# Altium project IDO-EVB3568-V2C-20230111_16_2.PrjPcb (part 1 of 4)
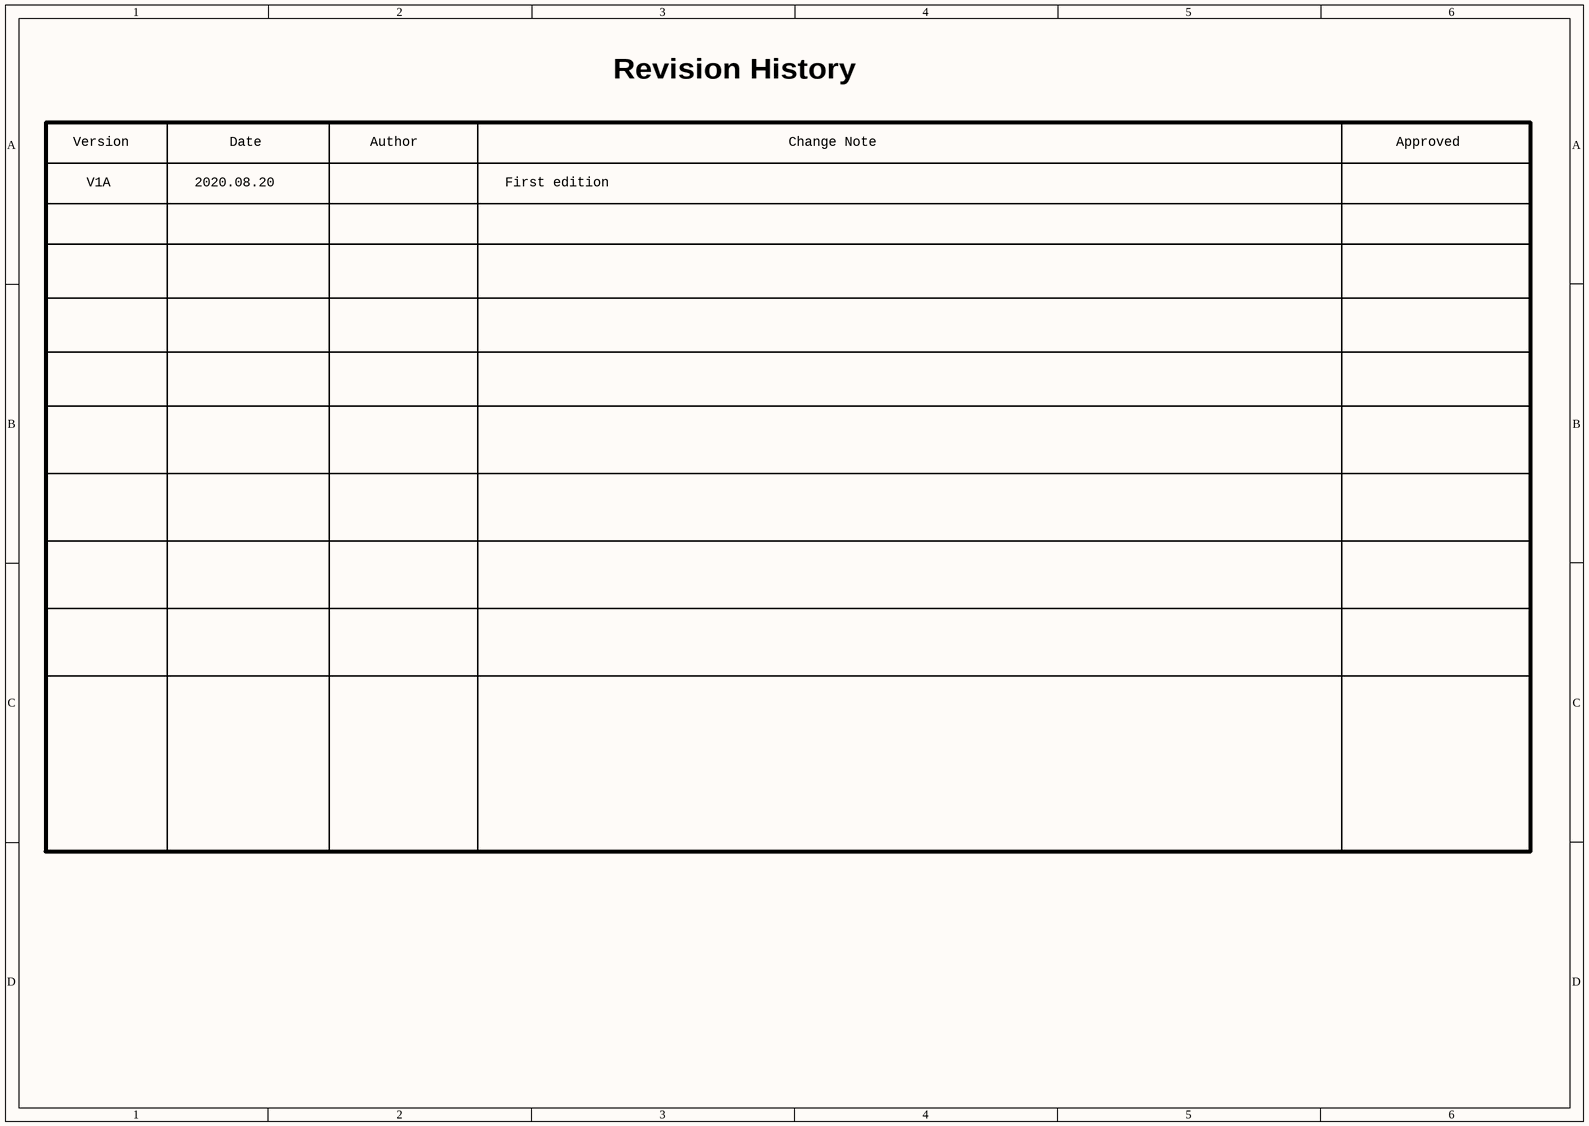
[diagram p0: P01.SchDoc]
20 sheets, 809 parts. Net scope: global (net labels, ports and power ports of the same name join across sheets).
Sheets:
  P01.SchDoc
  P02.SchDoc
  P03.SchDoc
  P04.SchDoc
  P05.SchDoc
  P06.SchDoc
  P07.SchDoc
  P08.SchDoc
  P09.SchDoc
  P10.SchDoc
  P11.SchDoc
  P12.SchDoc
  P13.SchDoc
  P14.SchDoc
  P15.SchDoc
  P16.SchDoc
  P17.SchDoc
  P18.SchDoc
  P19.SchDoc
  P20.SchDoc

## Sheet P01.SchDoc
size 297 x 209 mm

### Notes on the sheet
- Revision History
- Version
- V1A
- 2020.08.20
- Date
- Author
- First edition
- Change Note
- Approved

## Sheet P02.SchDoc
size 594 x 420 mm
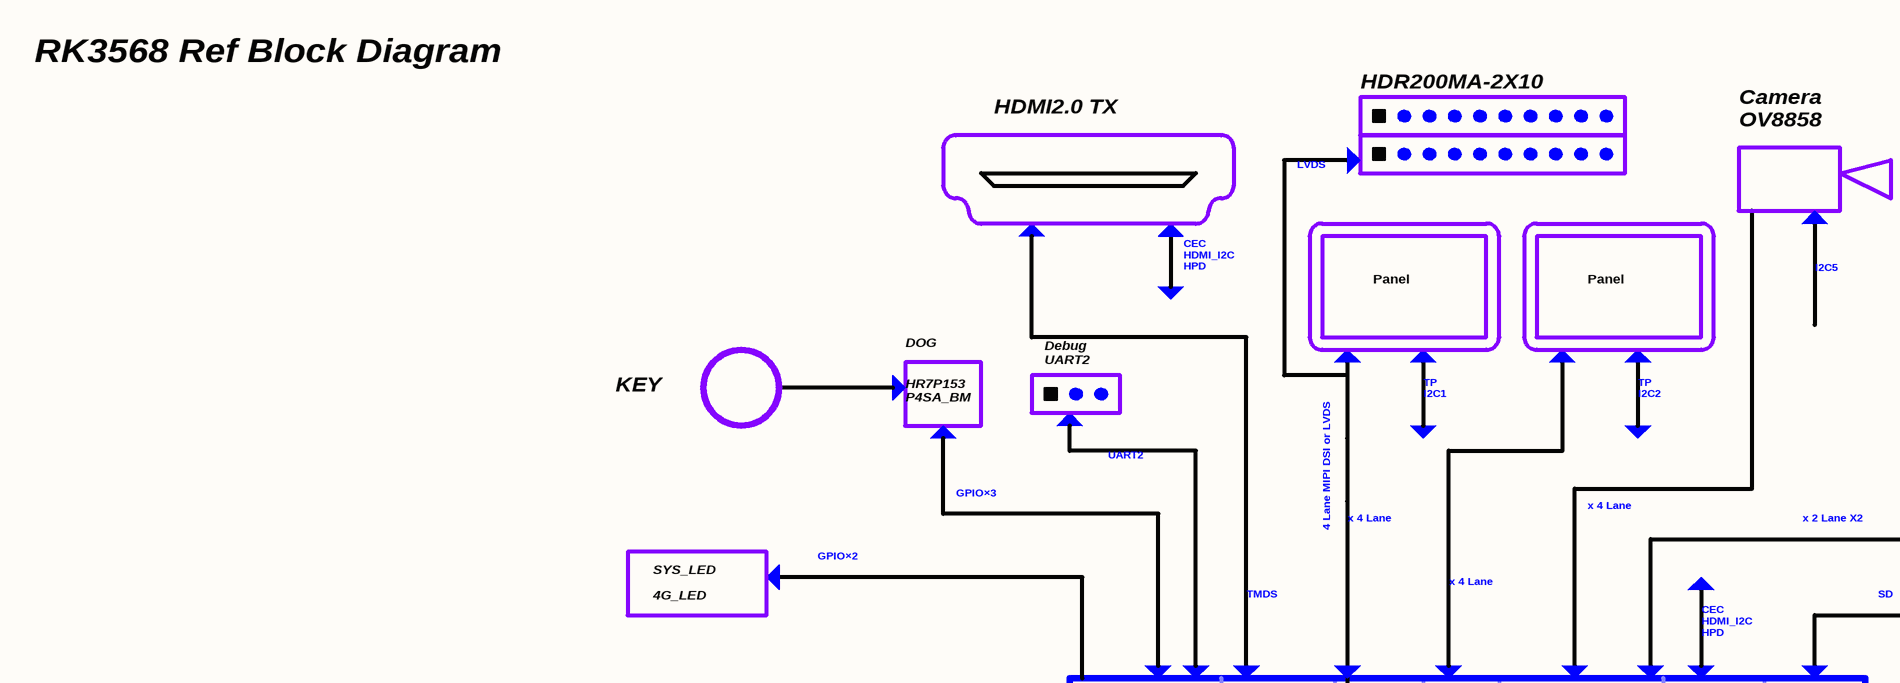
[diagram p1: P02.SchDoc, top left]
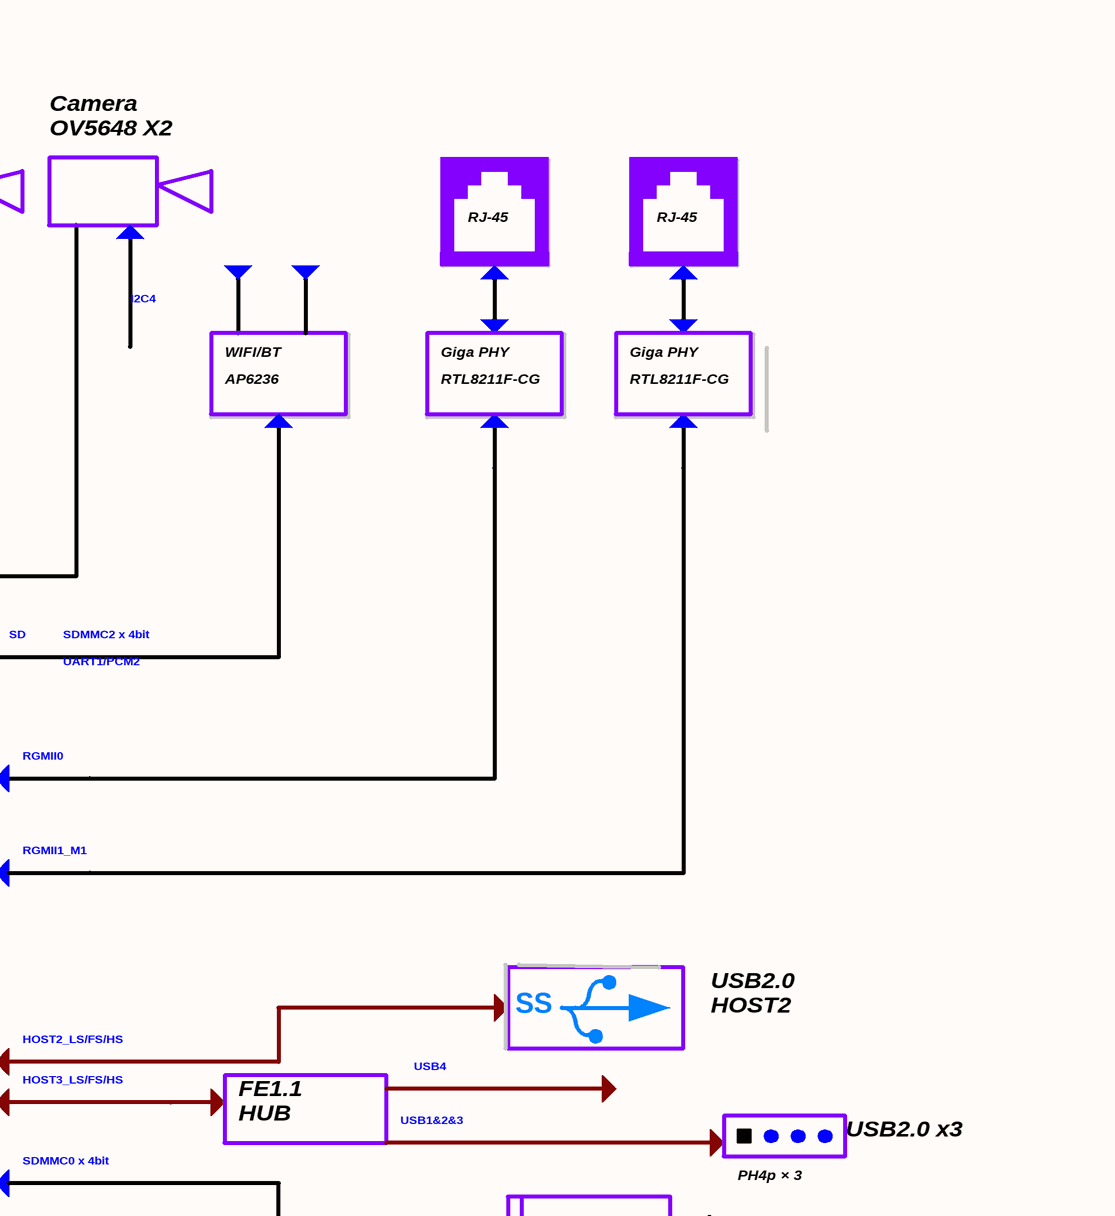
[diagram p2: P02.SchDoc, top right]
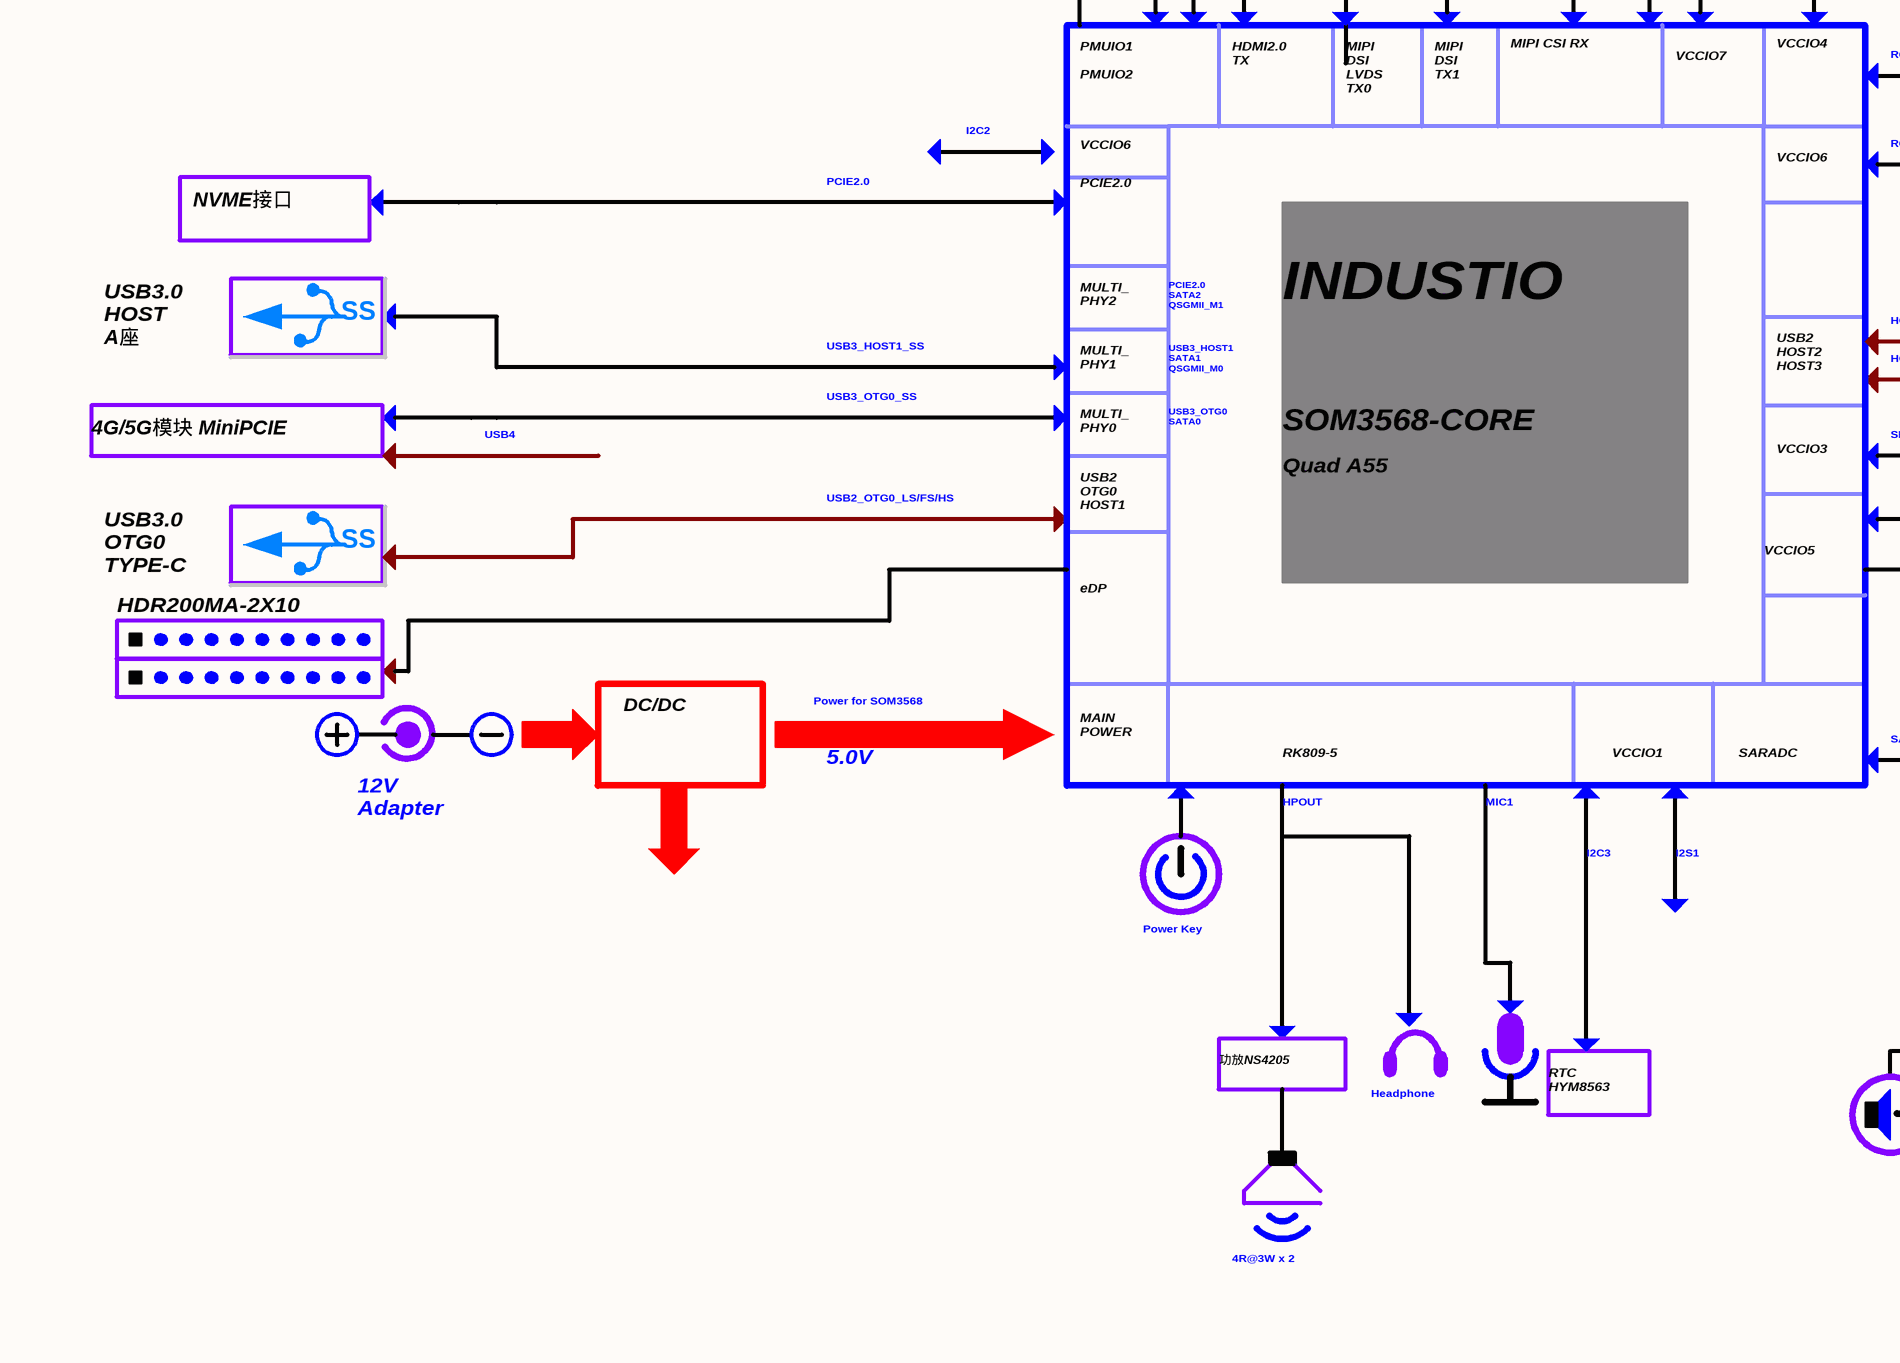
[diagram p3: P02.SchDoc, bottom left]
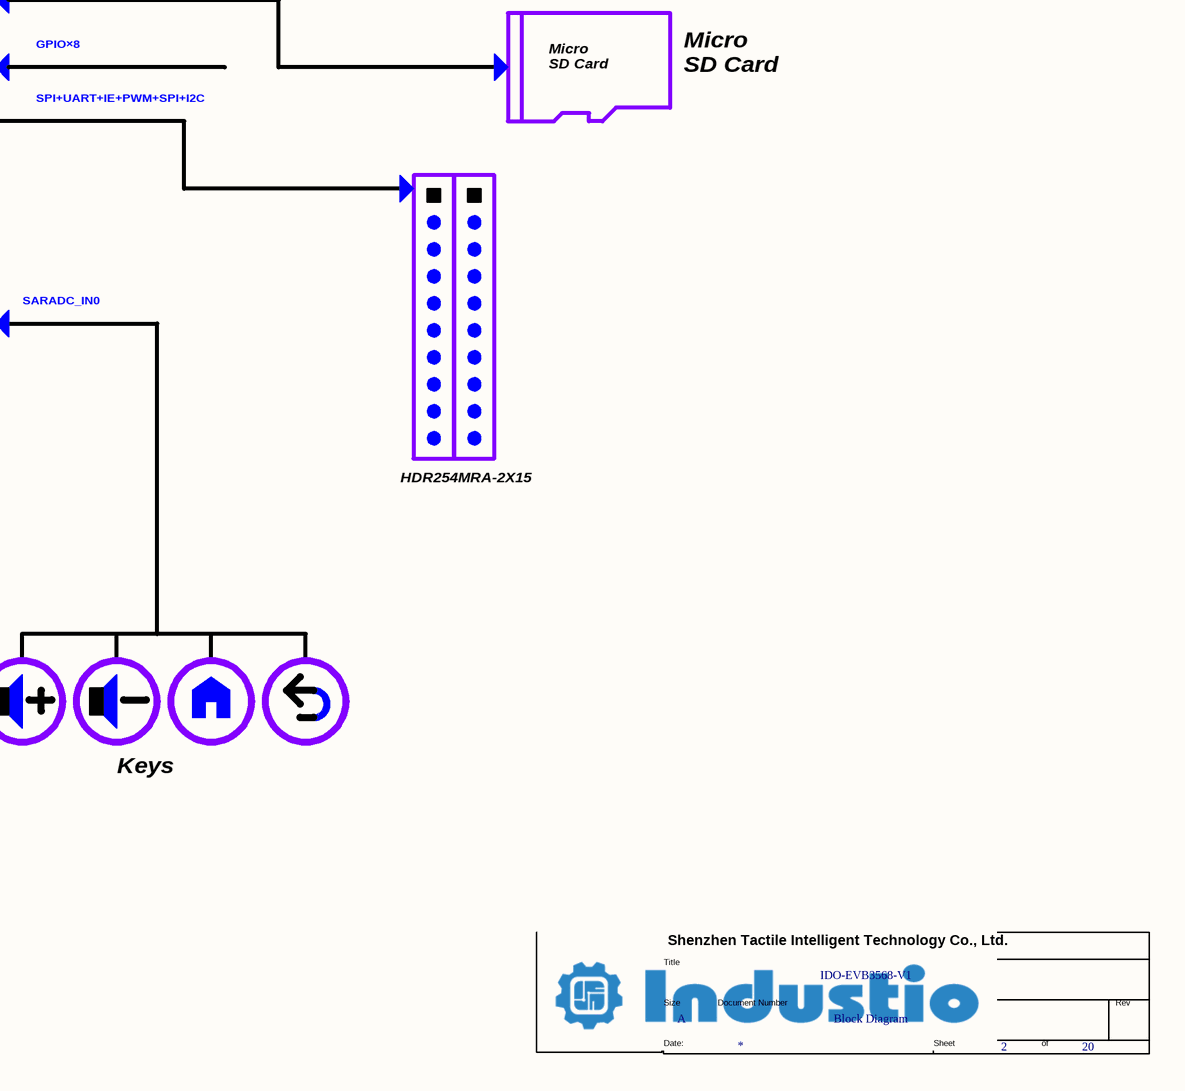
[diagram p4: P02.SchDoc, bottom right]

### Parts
(Parts that share a designator on the sheet are numbered #1, #2 ... from top to bottom, then left to right.)
*#1  Doc: Block Diagram  Title: IDO-EVB3568-V1  Page Size: A  Page Number: 2  Page Count: 20  (hidden comment: TitleBlock1)  (graphical)

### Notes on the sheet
- RK3568 Ref Block Diagram
- HDR200MA-2X10
- Camera
  OV8858
- Camera
  OV5648 X2
- HDMI2.0 TX
- LVDS
- CEC
  HDMI_I2C
  HPD
- RJ-45
- Panel
- I2C5
- I2C4
- DOG
- Debug
  UART2
- AP6236
- WIFI/BT
- RTL8211F-CG
- Giga PHY
- KEY
- HR7P153
  P4SA_BM
- TP
  I2C1
- TP
  I2C2
- UART2
- GPIO×3
- 4 Lane MIPI DSI or LVDS
- x 4 Lane
- x 2 Lane X2
- 4G_LED
- SYS_LED
- GPIO×2
- TMDS
- SD
- SDMMC2 x 4bit
- UART1/PCM2
- PMUIO1
  PMUIO2
- HDMI2.0
  TX
- MIPI
  DSI
  LVDS
  TX0
- MIPI
  DSI
  TX1
- MIPI CSI RX
- VCCIO7
- VCCIO4
- RGMII0
- I2C2
- VCCIO6
- RGMII1_M1
- NVME接口
- PCIE2.0
- USB3.0
  HOST
  A座
- MULTI_
  PHY2
- PCIE2.0
  SATA2
  QSGMII_M1
- USB2.0
  HOST2
- SS
- MULTI_
  PHY1
- USB3_HOST1
  SATA1
  QSGMII_M0
- INDUSTIO
- USB2
  HOST2
  HOST3
- HOST2_LS/FS/HS
- USB3_OTG0_SS
- USB3_HOST1_SS
- MULTI_
  PHY0
- USB3_OTG0
  SATA0
- HOST3_LS/FS/HS
- FE1.1
  HUB
- USB1&2&3
- USB4
- USB2.0 x3
- 4G/5G模块 MiniPCIE
- USB2
  OTG0
  HOST1
- SOM3568-CORE
- VCCIO3
- SDMMC0 x 4bit
- PH4p × 3
- USB3.0
  OTG0
  TYPE-C
- USB2_OTG0_LS/FS/HS
- Quad A55
- GPIO×8
- Micro
  SD Card
- eDP
- VCCIO5
- SPI+UART+IE+PWM+SPI+I2C
- DC/DC
- Power for SOM3568
- MAIN
  POWER
- 12V
  Adapter
- 5.0V
- RK809-5
- VCCIO1
- SARADC
- SARADC_IN0
- HPOUT
- MIC1
- I2C3
- I2S1
- HDR254MRA-2X15
- Power Key
- 功放NS4205
- Headphone
- RTC
  HYM8563
- Keys
- 4R@3W x 2

## Sheet P03.SchDoc
size 594 x 420 mm
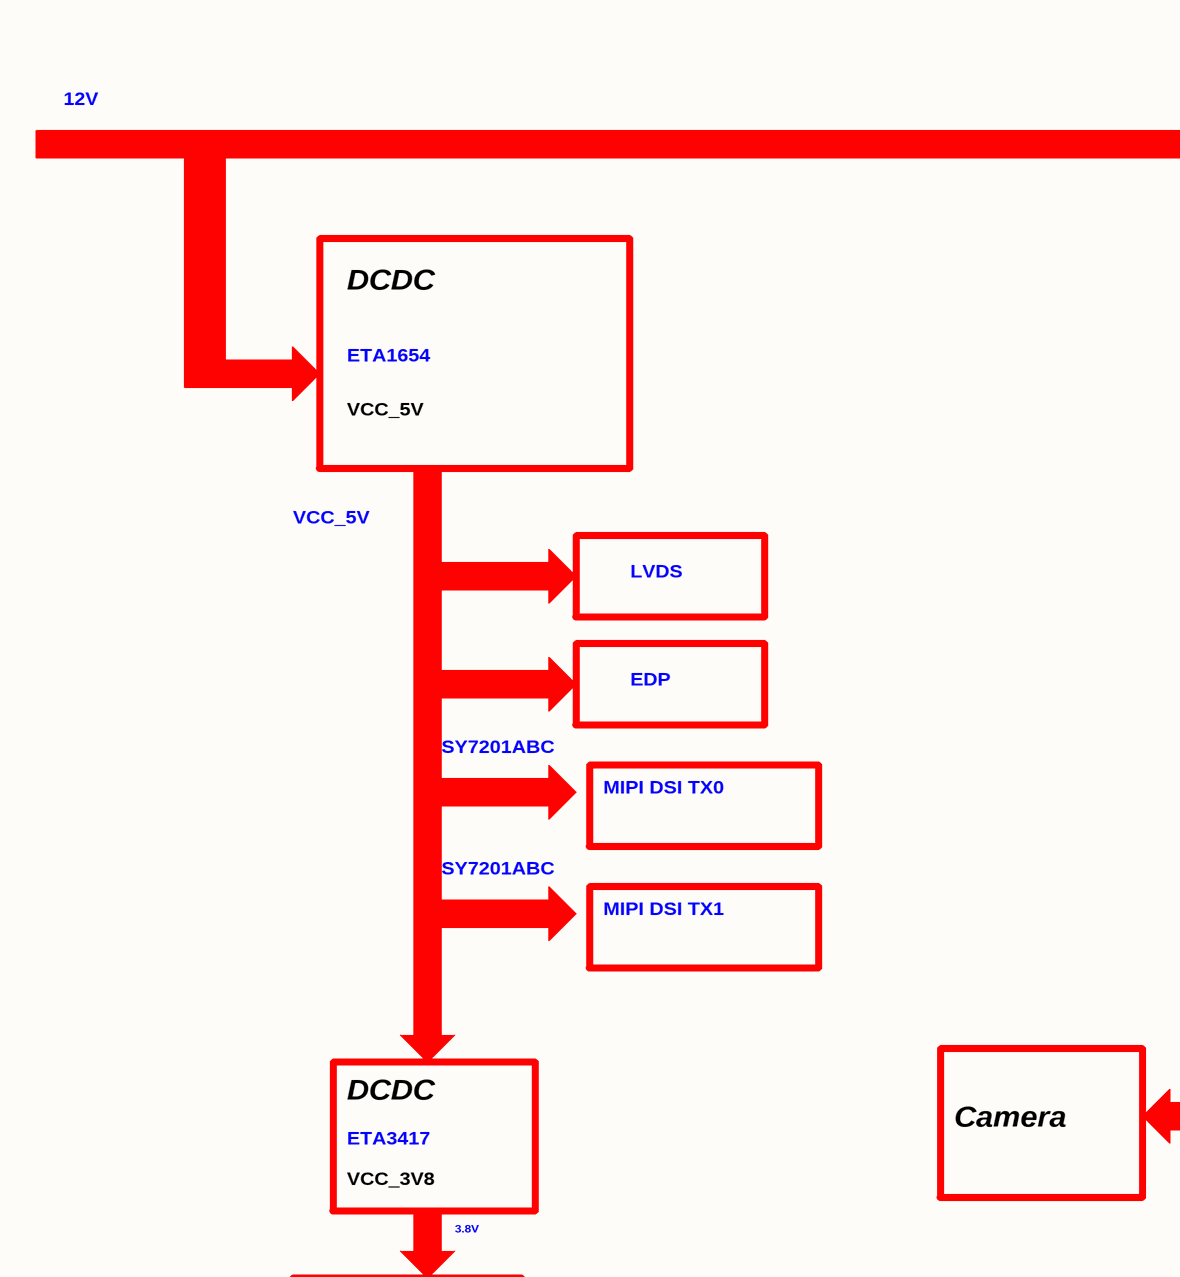
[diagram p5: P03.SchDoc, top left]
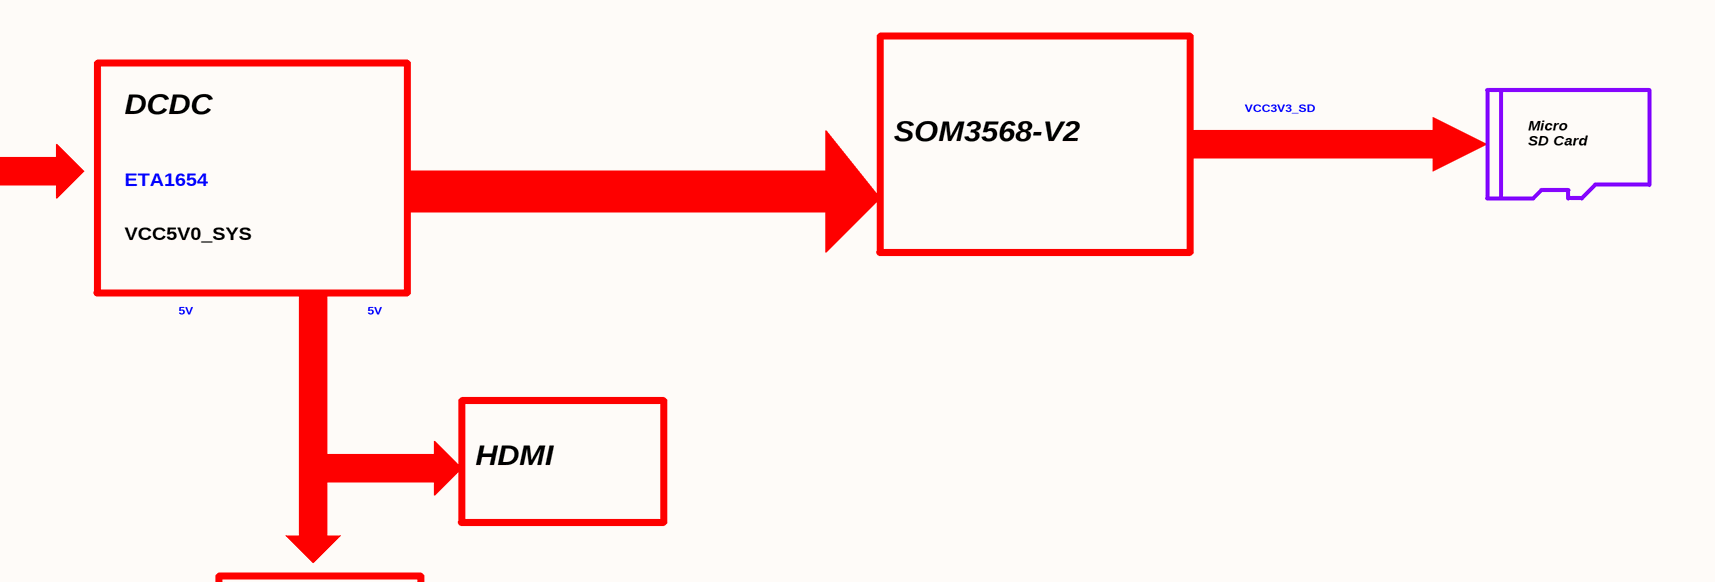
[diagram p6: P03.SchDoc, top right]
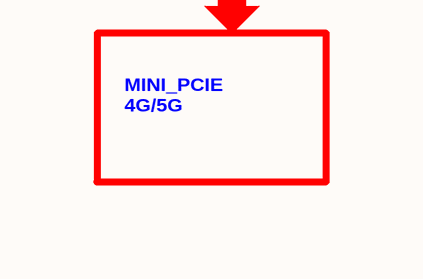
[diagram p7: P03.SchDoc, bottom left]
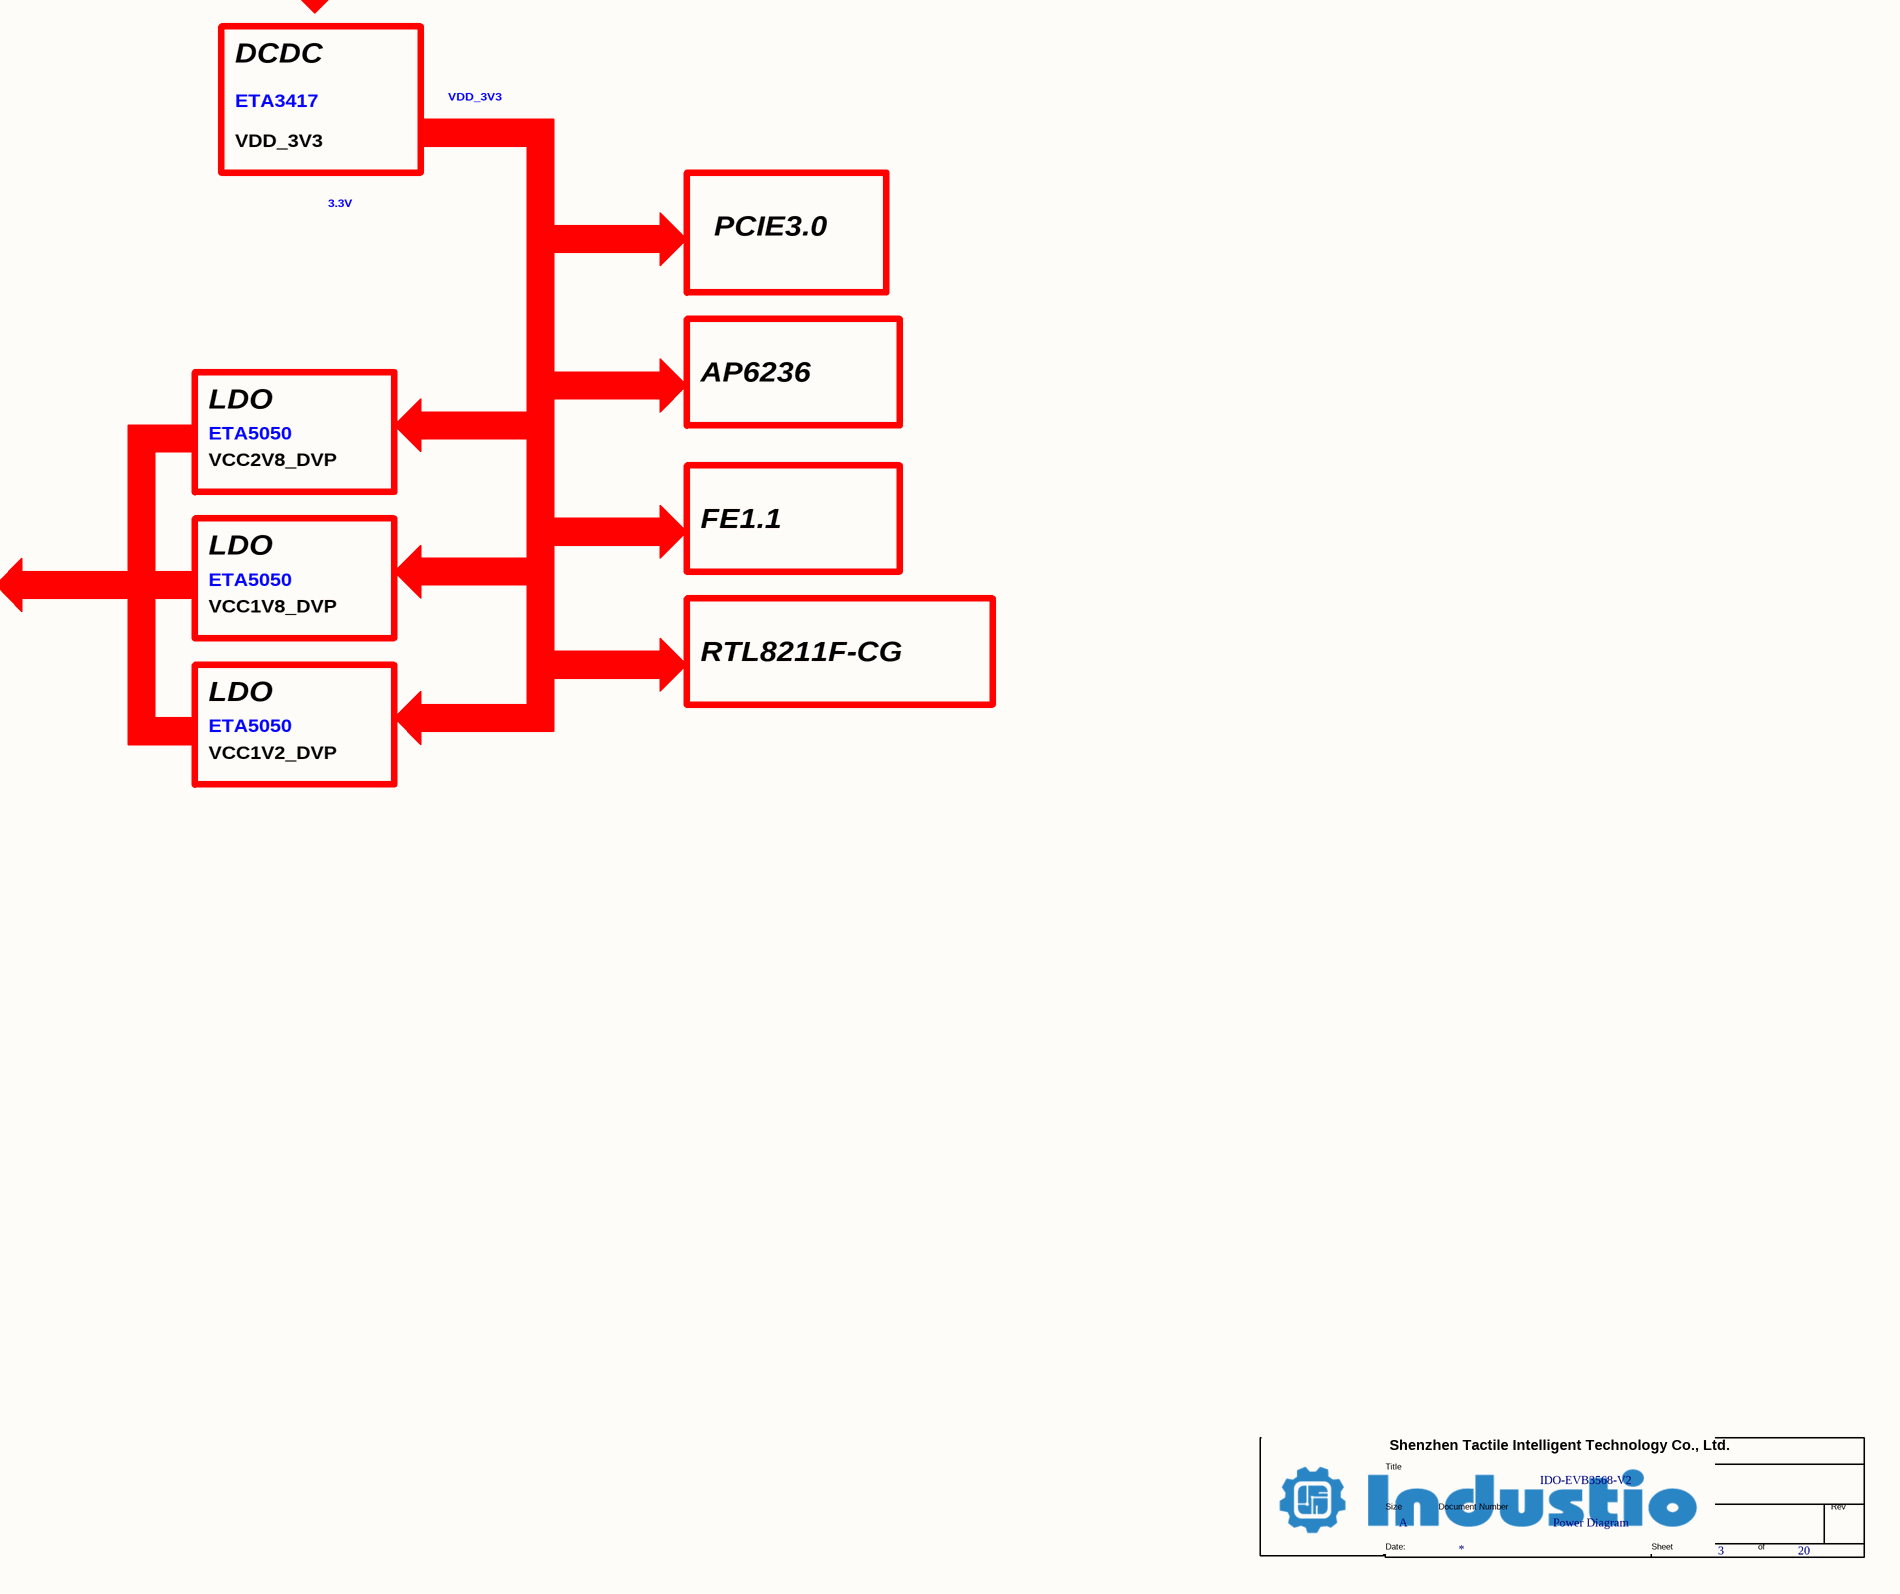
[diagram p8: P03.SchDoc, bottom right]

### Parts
(Parts that share a designator on the sheet are numbered #1, #2 ... from top to bottom, then left to right.)
*#2  Doc: Power Diagram  Title: IDO-EVB3568-V2  Page Size: A  Page Number: 3  Page Count: 20  (hidden comment: TitleBlock1)  (graphical)

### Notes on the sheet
- 12V
- DCDC
- SOM3568-V2
- VCC3V3_SD
- Micro
  SD Card
- ETA1654
- VCC5V0_SYS
- 5V
- VCC_5V
- HDMI
- LVDS
- ETA3417
- VDD_3V3
- EDP
- SY7201ABC
- MIPI DSI TX0
- 3.3V
- PCIE3.0
- MIPI DSI TX1
- AP6236
- LDO
- ETA5050
- VCC2V8_DVP
- FE1.1
- Camera
- VCC_3V8
- VCC1V8_DVP
- RTL8211F-CG
- 3.8V
- MINI_PCIE
  4G/5G
- VCC1V2_DVP

## Sheet P04.SchDoc
size 420 x 297 mm
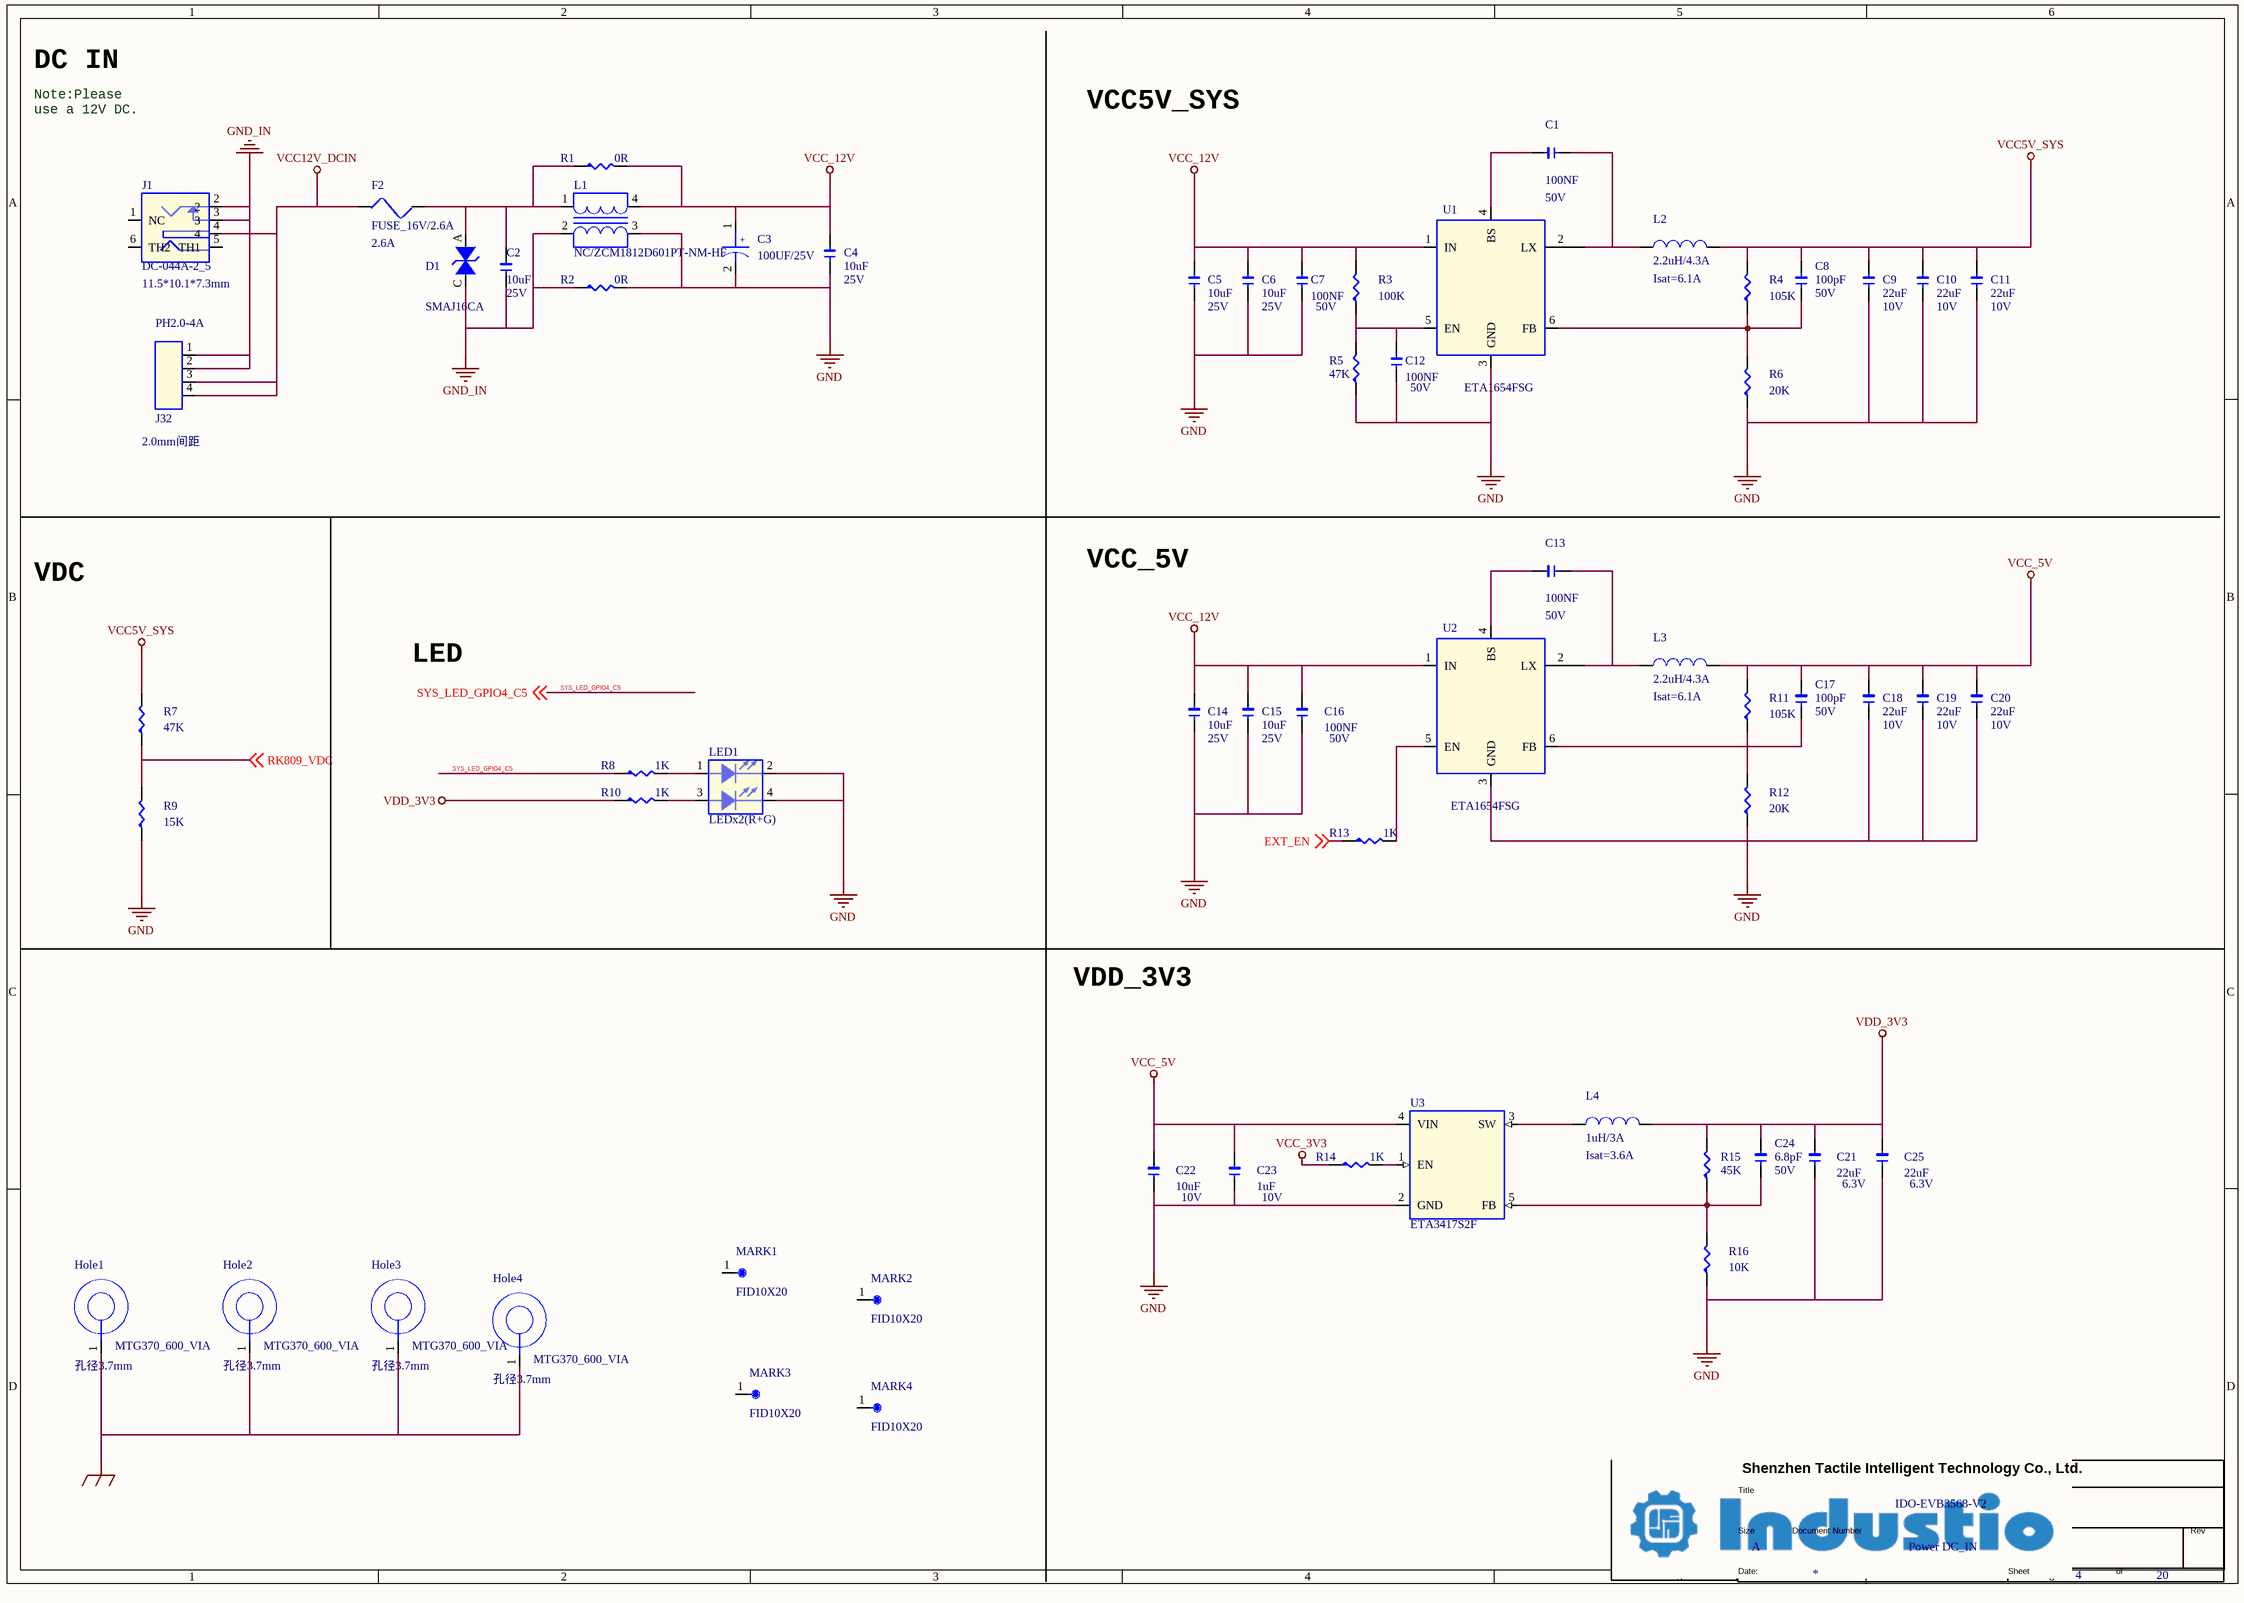
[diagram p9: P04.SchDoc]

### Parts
(Parts that share a designator on the sheet are numbered #1, #2 ... from top to bottom, then left to right.)
*#3  Doc: Power DC_IN  Title: IDO-EVB3568-V2  Page Size: A  Page Number: 4  Page Count: 20  (hidden comment: TitleBlock1)  (graphical)
C1  100NF  DSC2: 50V  [1206]
C2  10uF  DSC2: 25V  [1206]
C3  100UF/25V  [CAPAE660X770]
C4  10uF  DSC2: 25V  [1206]
C5  10uF  DSC2: 25V  [1206]
C6  10uF  DSC2: 25V  [1206]
C7  100NF  DSC2: 50V  [1206]
C8  100pF  DSC2: 50V  [1206]
C9  22uF  DSC2: 10V  [1206]
C10  22uF  DSC2: 10V  [1206]
C11  22uF  DSC2: 10V  [1206]
C12  100NF  DSC2: 50V  [1206]
C13  100NF  DSC2: 50V  [1206]
C14  10uF  DSC2: 25V  [1206]
C15  10uF  DSC2: 25V  [1206]
C16  100NF  DSC2: 50V  [1206]
C17  100pF  DSC2: 50V  [1206]
C18  22uF  DSC2: 10V  [1206]
C19  22uF  DSC2: 10V  [1206]
C20  22uF  DSC2: 10V  [1206]
C21  22uF  DSC2: 6.3V  [1206]
C22  10uF  DSC2: 10V  [1206]
C23  1uF  DSC2: 10V  [1206]
C24  6.8pF  DSC2: 50V  [1206]
C25  22uF  DSC2: 6.3V  [1206]
D1  SMAJ16CA  [SMA_DO-214AC]
F2  FUSE_16V/2.6A  DSC2: 2.6A  [SMD1812]
Hole1  MTG370_600_VIA  DSC2: 孔径3.7mm  [MH276_091]
Hole2  MTG370_600_VIA  DSC2: 孔径3.7mm  [MH276_091]
Hole3  MTG370_600_VIA  DSC2: 孔径3.7mm  [MH276_091]
Hole4  MTG370_600_VIA  DSC2: 孔径3.7mm  [MH276_091]
J1  DC-044A-2_5  DSC2: 11.5*10.1*7.3mm  [DC-044A-2_0-DIP]
J32  PH2.0-4A  DSC2: 2.0mm间距  [PH200-4A]
L1  NC/ZCM1812D601PT-NM-HF  [CMLP-ACM4532]
L2  2.2uH/4.3A  DSC2: Isat=6.1A  [IND_404020]
L3  2.2uH/4.3A  DSC2: Isat=6.1A  [IND_404020]
L4  1uH/3A  DSC2: Isat=3.6A  [IND_252012]
LED1  LEDx2(R+G)  [LED_P254_2X2DIP]
MARK1  FID10X20  [E-Mark-TP-02-100x]
MARK2  FID10X20  [E-Mark-TP-02-100x]
MARK3  FID10X20  [E-Mark-TP-02-100x]
MARK4  FID10X20  [E-Mark-TP-02-100x]
R1  0R  [R0805]
R2  0R  [R0805]
R3  100K  [R0402]
R4  105K  [R0402]
R5  47K  [R0402]
R6  20K  [R0402]
R7  47K  [R0402]
R8  1K  [R0402]
R9  15K  [R0402]
R10  1K  [R0402]
R11  105K  [R0402]
R12  20K  [R0402]
R13  1K  [R0402]
R14  1K  [R0402]
R15  45K  [R0402]
R16  10K  [R0402]
U1  ETA1654FSG  [SOT563]
U2  ETA1654FSG  [SOT563]
U3  ETA3417S2F  [SOT23-5]

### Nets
GND: C3.2 C4.1 C5.1 C6.1 C7.1 C9.1 C10.1 C11.1 C12.1 C14.1 C15.1 C16.1 C18.1 C19.1 C20.1 C21.1 C22.1 C23.1 C25.1 L1.3 LED1.2 LED1.4 R2.2 R5.1 R6.1 R9.1 R12.1 R16.1 U1.3(GND) U2.3(GND) U3.2(GND)  [project net EDP_TX_AUXP_]
GND_EARTH: Hole1.1 Hole2.1 Hole3.1 Hole4.1
GND_IN: C2.1 D1.C(I/O1) J1.2 J1.3 J32.1 J32.2 L1.2 R2.1
VCC5V_SYS: C8.2 C9.2 C10.2 C11.2 L2.2 R4.2 R7.2
VCC12V_DCIN: F2.1 J1.4 J32.3 J32.4
VCC_3V3: R14.1
VCC_5V: C17.2 C18.2 C19.2 C20.2 C22.2 C23.2 L3.2 R11.2 U3.4(VIN)
VCC_12V: C3.1 C4.2 C5.2 C6.2 C7.2 C14.2 C15.2 C16.2 L1.4 R1.2 R3.2 U1.1(IN) U2.1(IN)
VDD_3V3: C21.2 C24.2 C25.2 L4.2 R10.1 R15.2
EXT_EN: R13.1 ; off-sheet EXT_EN
RK809_VDC: R7.1 R9.2 ; off-sheet RK809_VDC
SYS_LED_GPIO4_C5: R8.1 ; off-sheet SYS_LED_GPIO4_C5
NetC1_1: C1.1 L2.1 U1.2(LX)
NetC1_2: C1.2 U1.4(BS)
NetC2_2: C2.2 D1.A(I/O2) F2.2 L1.1 R1.1
NetC8_1: C8.1 R4.1 R6.2 U1.6(FB)
NetC12_2: C12.2 R3.1 R5.2 U1.5(EN)
NetC13_1: C13.1 L3.1 U2.2(LX)
NetC13_2: C13.2 U2.4(BS)
NetC17_1: C17.1 R11.1 R12.2 U2.6(FB)
NetC24_1: C24.1 R15.1 R16.2 U3.5(FB)
NetL4_1: L4.1 U3.3(SW)
NetLED1_1: LED1.1 R8.2
NetLED1_3: LED1.3 R10.2
NetR13_2: R13.2 U2.5(EN)
NetR14_2: R14.2 U3.1(EN)

Not connected (* = marked no-connect by the designer): J1 1(NC) 5(TH1) 6(TH2); MARK1 1; MARK2 1; MARK3 1; MARK4 1

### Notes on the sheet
- DC IN
- Note:Please
  use a 12V DC.
- VCC5V_SYS
- VDC
- VCC_5V
- LED
- VDD_3V3

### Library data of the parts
C1 C12 = C-0402_Dup1: Manufacture: 三星¦国巨¦村田; Part Name: 贴片电容; Part Number: C020102120061; ID: 61; DSC3: X7R; DSC1: ±10%; ERP Number: 1010200128; PCB Footprint: C0402
C2 C14 C15 = C-0805: Manufacture: 三星¦国巨¦村田; Part Name: 贴片电容; Part Number: C020102120074; PCB Footprint: C0805; ID: 74; DSC3: X5R; DSC1: ±10%; ERP Number: 1010200144
C3 = C-AL-SMD: Manufacture: 先科¦立隆¦三莹; Part Name: 贴片铝电容; Part Number: C020302140006; ID: 6; DSC7: LZ1E101M-CRE77(ST); DSC6: SMD,6.3x7.7mm; DSC5: -55~105 ℃; DSC4: 2000H; DSC3: 低阻抗; DSC2: 25V; DSC1: ±20%; ERP Number: 1010200266
C4 = C-0805: Part Number: C020102120074; Part Name: 贴片电容; Manufacture: 三星¦国巨¦村田; ERP Number: 1010200144; DSC1: ±10%; DSC3: X5R; ID: 74; PCB Footprint: C0805
C5 C6 = C-0805: Manufacture: 三星¦国巨¦村田; Part Name: 贴片电容; Part Number: C020102120074; ID: 74; DSC3: X5R; DSC1: ±10%; ERP Number: 1010200144; PCB Footprint: C0805
C7 = C-0402_Dup1: Part Number: C020102120061; Part Name: 贴片电容; Manufacture: 三星¦国巨¦村田; ERP Number: 1010200128; DSC1: ±10%; DSC3: X7R; ID: 61; PCB Footprint: C0402
C8 C17 = C-0402_Dup1: Part Number: C020102120040; Part Name: 贴片电容; Manufacture: 三星¦国巨¦村田; PCB Footprint: C0402; ERP Number: 1010200152; DSC1: ±5%; DSC3: C0G; ID: 40
C9-C11 C18-C20 = C-0805: Manufacture: 三星¦国巨¦村田; Part Name: 贴片电容; Part Number: C020102120075; PCB Footprint: C0603; ID: 75; DSC3: X5R; DSC1: ±20%
C13 C16 = C-0402_Dup1: Manufacture: 三星¦国巨¦村田; Part Name: 贴片电容; Part Number: C020102120061; PCB Footprint: C0402; ID: 61; DSC3: X7R; DSC1: ±10%; ERP Number: 1010200128
C21 C25 = C-0603_Dup1: Part Number: C020102120072; Part Name: 贴片电容; Manufacture: 三星¦国巨¦村田; PCB Footprint: C0603; ERP Number: 1010200133; DSC1: ±20%; DSC3: X5R; ID: 72
C22 = C-0603_Dup1: Manufacture: 三星¦国巨¦村田; Part Name: 贴片电容; Part Number: C020102120071; PCB Footprint: C0603; ID: 71; DSC3: X5R; DSC1: ±20%; ERP Number: 1010200076
C23 = C-0402_Dup1: Part Number: C020102120064; Part Name: 贴片电容; Manufacture: 三星¦国巨¦村田; PCB Footprint: C0402; ERP Number: 1010200054; DSC1: ±10%; DSC3: X5R; ID: 64
C24 = C-0402_Dup2: Manufacture: 三星¦国巨¦村田; Part Name: 贴片电容; Part Number: C020102120018; PCB Footprint: C0402; ID: 18; DSC3: C0G; DSC1: ±0.25PF; ERP Number: 1010200056
D1 = DI-TVS-D: ESD 0402; Part Number: C040602260004; Manufacture P/N: MLVG04021R0UV18; Manufacturer: INPAQ; Manufacture: 硕凯; Part Name: TVS; PN Type: Varistor; ID: 4; DSC6: Ppp=400W; DSC5: Ipp=15.4A; DSC4: Vc=26V; DSC3: VBR=17.8V; DSC2: Vrwm=16V; DSC1: 双向
F2 = FUSE-SMD1812: Part Number: C160102670007; Part Name: 自恢复保险丝; Manufacture: 硕凯; DSC1: 16V; DSC3: SCF260-16-1812RB; ID: 7
Hole1-Hole4 = MH-NOE: Part Number: CAD; Part Name: 镀锡(金)焊盘固定孔; ID: 33; DSC3: 8个过孔; DSC1: 顶层和底层焊盘直径=6mm
J1 = J-DC-044A-2_5: Part Number: J100103010003; Part Name: DC座; DSC1: 通孔弯针，内径2mm，2.5A，24VDC; DSC3: 通孔弯针; DSC4: DC-044A-2.5A-2.0(星坤); DSC5: DC0044A（九龙熹）; ID: 3
J32 = J-H-4P: Part Name: PH; Part Number: J020302820003; ID: 13; DSC6: X2016WV-04-46SN(星坤); DSC5: JLX-PH20-4A（九龙熹）; DSC4: 米黄色胶壳 耐高温; DSC3: 通孔180度直针; DSC1: 4p
L1 = L-CMLP: Part Name: 电源共模电感; Manufacture: 宗成; DSC2: 600Ω@100MHz; DSC3: 2.5A; DSC5: -40℃ ~ +85℃; DSC6: SMD_4P,4.5x3.2x2.8 mm; ID: 10
L2 L3 = L-IND: Manufacture: 宗成¦长江微电¦顺络; Part Number: C060202340020; Part Name: 功率电感; ID: 20; DSC8: ZCRH4020-2.2uH-M(宗成); DSC7: FHD4020S-2R2MT(长江微电); DSC6: WPN4020H2R2MT(顺络); DSC5: 4.0*4.0*2.0mm; DSC4: 48mΩ; DSC3: Irms=4.3A; DSC1: ±20%; ERP Number: 1010200404
L4 = L-IND: Manufacture: 宗成¦长江微电¦顺络; Part Name: 功率电感; ID: 52; DSC8: ZCRH252012-1uH-M(宗成); DSC7: FHD252012S-1R0MT(长江微电); DSC6: WPN252012H1R0MT(顺络); DSC5: 2.5*2.0*1.2mm; DSC4: 54mΩ; DSC3: Irms=3A; DSC1: ±20%
LED1 = D-LED-DIP-2: Part Number: C140202660018; Part Name: LED; DSC1: 双孔座2位黑色方形灯柱 90度弯脚 左正右负 上红下绿; ID: 22
MARK1 MARK2 MARK4 = MARK-FID10X20_1: Part Number: CAD; Part Name: 光学MARK点; ID: 9; PCB Footprint: FID1_0x2_3
MARK3 = MARK-FID10X20_0: Part Number: CAD; Part Name: 光学MARK点; ID: 9; PCB Footprint: FID1_0x2_3
R1 R2 = R-0805_Dup1: Part Name: 贴片电阻; Part Number: C011002081448; ERP Number: 1010200199; DSC1: ±1%; DSC2: 1/8W; ID: 1,448
R3 = R-0402_Dup4: Part Number: C011002080353; Part Name: 贴片电阻; ID: 353; DSC2: 1/16W; DSC1: ±5%; ERP Number: 1010200103
R4 R11 = R-0402_Dup4: Part Name: 贴片电阻; Part Number: C011002080978; DSC1: ±1%; DSC2: 1/16W; ID: 978
R5 R7 = R-0402_Dup4: Part Number: C011002080345; Part Name: 贴片电阻; ID: 345; DSC2: 1/16W; DSC1: ±5%; ERP Number: 1010200182
R6 R12 = R-0402_Dup4: Part Name: 贴片电阻; Part Number: C011002080889; ERP Number: 1010200333; DSC1: ±1%; DSC2: 1/16W; ID: 889
R8 R10 R13 R14 = R-0402_Dup4: Part Number: C011002080303; Part Name: 贴片电阻; ID: 303; DSC2: 1/16W; DSC1: ±5%; ERP Number: 1010200104
R9 = R-0402_Dup4: Part Number: C011002080332; Part Name: 贴片电阻; ID: 332; DSC2: 1/16W; DSC1: ±5%; ERP Number: 1010200258
R15 = R-0402_Dup4: Part Number: C011002080932; Part Name: 贴片电阻; ID: 932; DSC2: 1/16W; DSC1: ±1%
R16 = R-0402_Dup4: Part Name: 贴片电阻; Part Number: C011002080856; ERP Number: 1010200140; DSC1: ±1%; DSC2: 1/16W; ID: 856
U1 = U-ETA1654FSG: Part Name: DCDC; Part Number: C070209233998; Manufacture: ETA; DSC1: Vi=4.5-17V; DSC2: Vo=0.805-13.5V; DSC3: Io=4A; DSC4: Vfb=0.805V; DSC5: 0.97; DSC6: 600KHz; DSC7: 同步降压; Solder: 量产; ID: 44
U2 = U-ETA1654FSG: Manufacture: ETA; Part Number: C070209233998; Part Name: DCDC; ID: 44; Solder: 量产; DSC7: 同步降压; DSC6: 600KHz; DSC5: 0.97; DSC4: Vfb=0.805V; DSC3: Io=4A; DSC2: Vo=0.805-13.5V; DSC1: Vi=4.5-17V
U3 = U-ETA3417S2F: Manufacture: ETA; Part Number: C070205183984; Part Name: DCDC; ID: 43; Solder: 量产; DSC8: 替代料：TI的TLV62569DBVR/矽力杰SY8089AAAC; DSC7: 同步降压; DSC6: 3MHz; DSC4: Vfb=0.6V; DSC3: Io=2.5A; DSC2: Vo=0.6-7.0V; DSC1: Vi=2.6-7.0V

## Sheet P05.SchDoc
size 594 x 420 mm
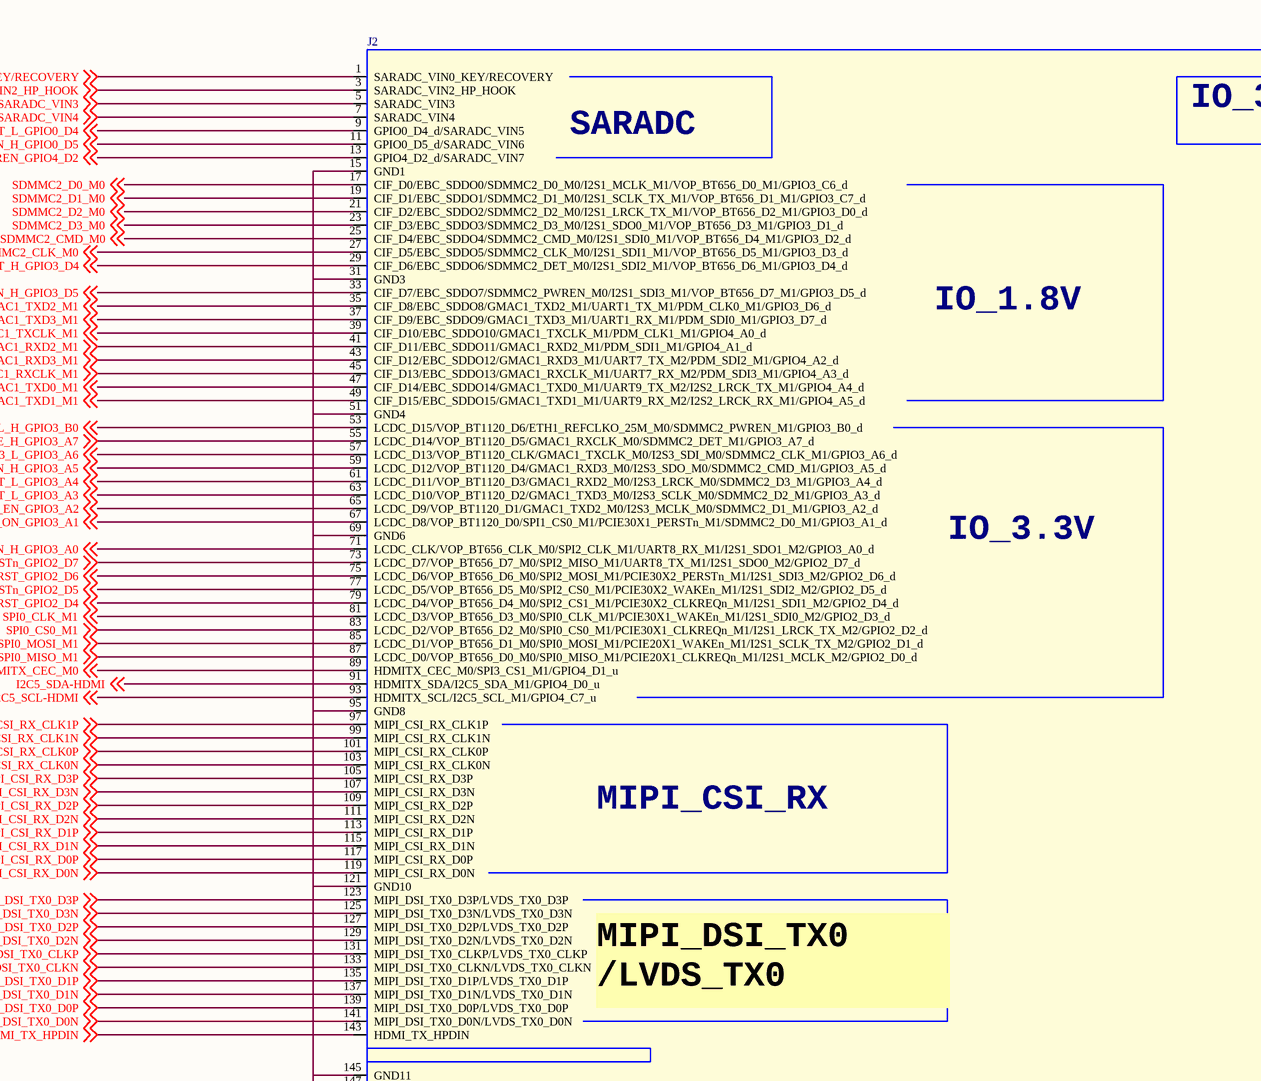
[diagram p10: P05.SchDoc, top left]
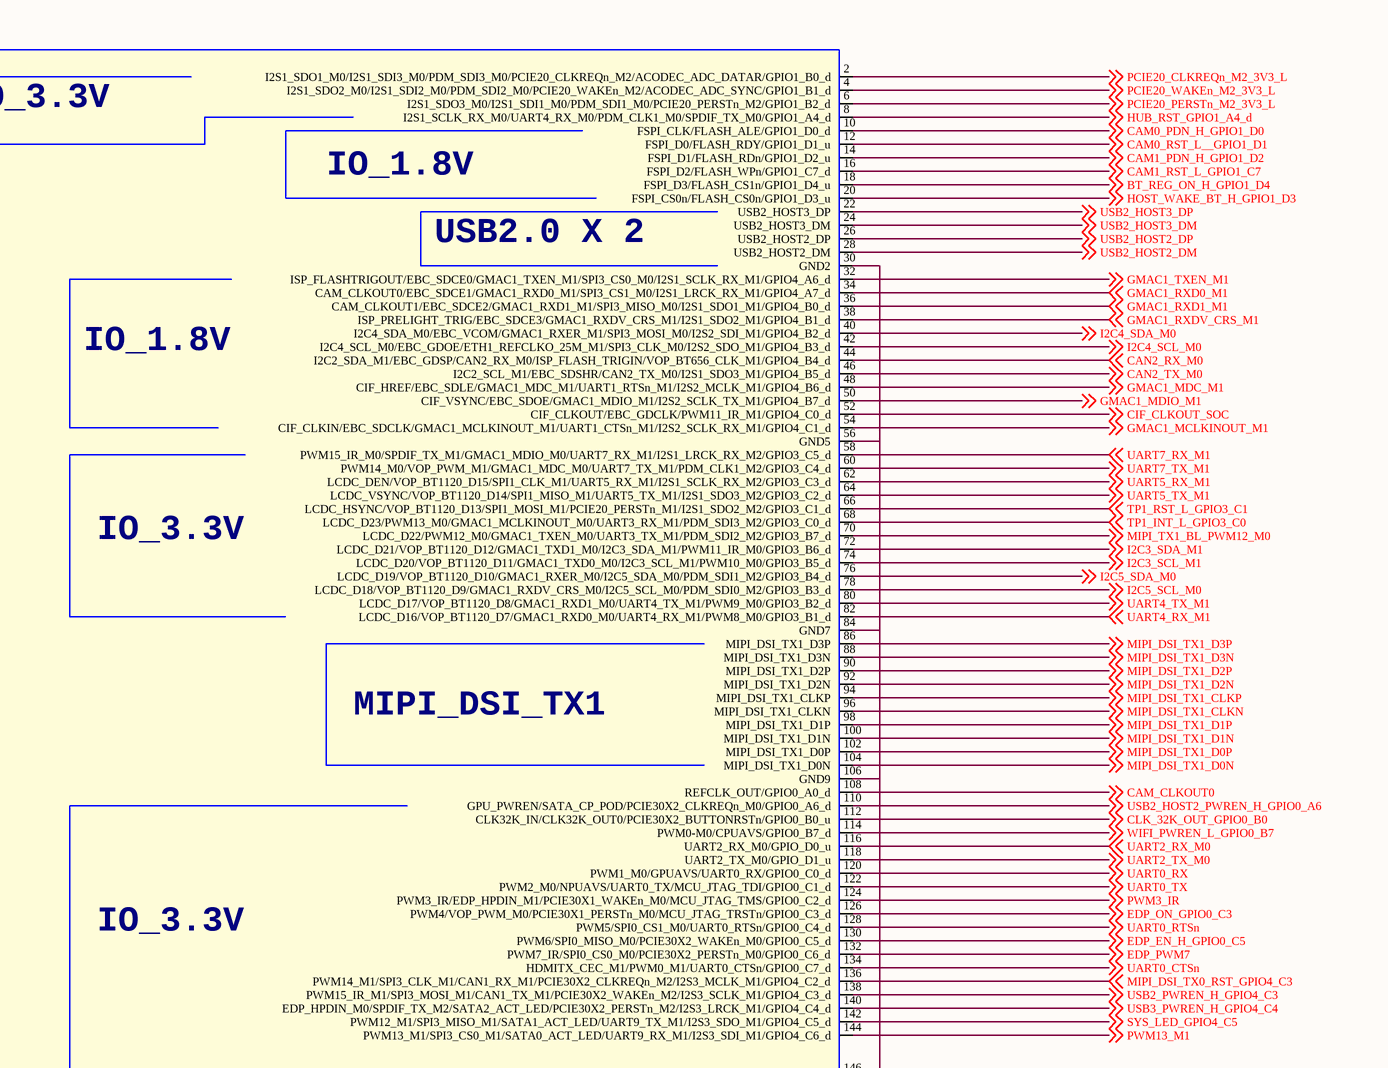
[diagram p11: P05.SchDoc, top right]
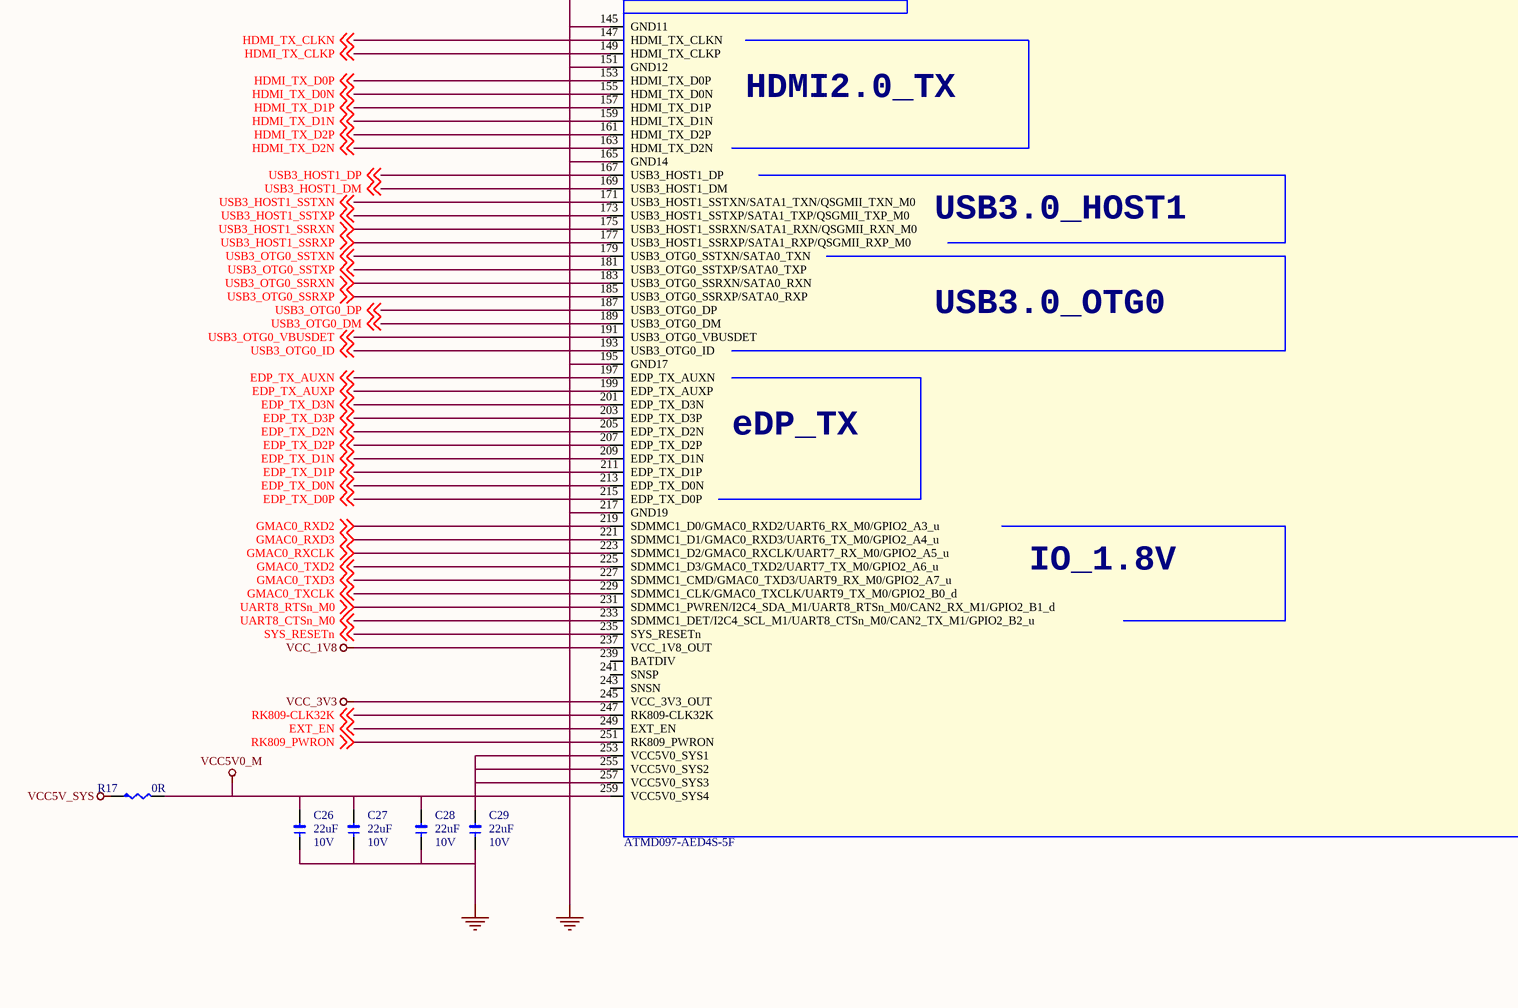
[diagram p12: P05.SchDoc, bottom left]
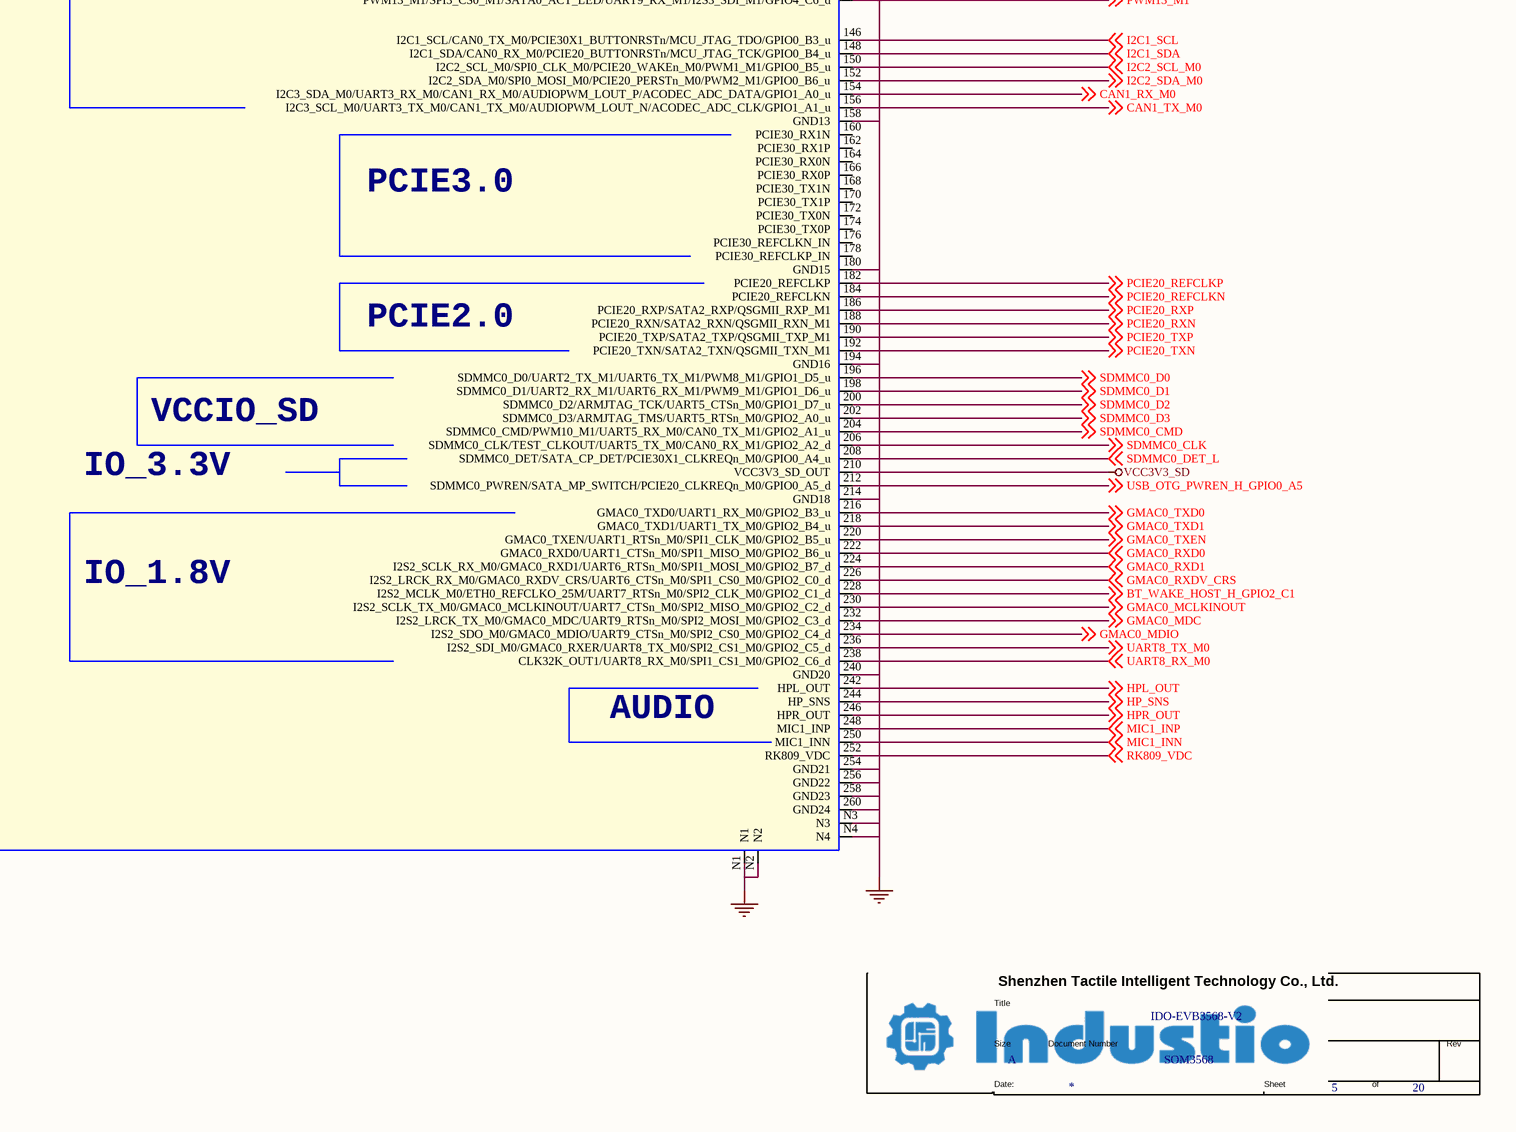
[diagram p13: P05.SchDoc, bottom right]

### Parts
(Parts that share a designator on the sheet are numbered #1, #2 ... from top to bottom, then left to right.)
*#4  Doc: SOM3568  Title: IDO-EVB3568-V2  Page Size: A  Page Number: 5  Page Count: 20  (hidden comment: TitleBlock1)  (graphical)
C26  22uF  DSC2: 10V  [1206]
C27  22uF  DSC2: 10V  [1206]
C28  22uF  DSC2: 10V  [1206]
C29  22uF  DSC2: 10V  [1206]
J2  ATMD097-AED4S-5F  [DDR4-SODIMM-260P-STD]
R17  0R  [R0805]

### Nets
GND: C26.1 C27.1 C28.1 C29.1 J2.15(GND1) J2.30(GND2) J2.31(GND3) J2.51(GND4) J2.56(GND5) J2.69(GND6) J2.84(GND7) J2.95(GND8) J2.106(GND9) J2.121(GND10) J2.145(GND11) J2.151(GND12) J2.158(GND13) J2.165(GND14) J2.180(GND15) J2.194(GND16) J2.195(GND17) J2.214(GND18) J2.217(GND19) J2.240(GND20) J2.254(GND21) J2.256(GND22) J2.258(GND23) J2.260(GND24) J2.N1 J2.N2 J2.N3 J2.N4  [project net EDP_TX_AUXP_]
VCC3V3_SD: J2.210(VCC3V3_SD_OUT)
VCC5V0_M: C26.2 C27.2 C28.2 C29.2 J2.253(VCC5V0_SYS1) J2.255(VCC5V0_SYS2) J2.257(VCC5V0_SYS3) J2.259(VCC5V0_SYS4) R17.2
VCC5V_SYS: R17.1
VCC_1V8: J2.237(VCC_1V8_OUT)
VCC_3V3: J2.245(VCC_3V3_OUT)
4G_PWREN_H_GPIO0_D5: J2.11(GPIO0_D5_d/SARADC_VIN6) ; off-sheet 4G_PWREN_H_GPIO0_D5
4G_RESET_L_GPIO0_D4: J2.9(GPIO0_D4_d/SARADC_VIN5) ; off-sheet 4G_RESET_L_GPIO0_D4  [project net 4G_5G_RESET]
BT_REG_ON_H_GPIO1_D4: J2.18(FSPI_D3/FLASH_CS1n/GPIO1_D4_u) ; off-sheet BT_REG_ON_H_GPIO1_D4
BT_WAKE_HOST_H_GPIO2_C1: J2.228(I2S2_MCLK_M0/ETH0_REFCLKO_25M/UART7_RTSn_M0/SPI2_CLK_M0/GPIO2_C1_d) ; off-sheet BT_WAKE_HOST_H_GPIO2_C1
CAM0_PDN_H_GPIO1_D0: J2.10(FSPI_CLK/FLASH_ALE/GPIO1_D0_d) ; off-sheet CAM0_PDN_H_GPIO1_D0
CAM0_RST_L__GPIO1_D1: J2.12(FSPI_D0/FLASH_RDY/GPIO1_D1_u) ; off-sheet CAM0_RST_L__GPIO1_D1
CAM1_PDN_H_GPIO1_D2: J2.14(FSPI_D1/FLASH_RDn/GPIO1_D2_u) ; off-sheet CAM1_PDN_H_GPIO1_D2
CAM1_RST_L_GPIO1_C7: J2.16(FSPI_D2/FLASH_WPn/GPIO1_C7_d) ; off-sheet CAM1_RST_L_GPIO1_C7
CAM_CLKOUT0: J2.108(REFCLK_OUT/GPIO0_A0_d) ; off-sheet CAM_CLKOUT0
CAMERA_PWREN_GPIO4_D2: J2.13(GPIO4_D2_d/SARADC_VIN7) ; off-sheet CAMERA_PWREN_GPIO4_D2
CAN1_RX_M0: J2.154(I2C3_SDA_M0/UART3_RX_M0/CAN1_RX_M0/AUDIOPWM_LOUT_P/ACODEC_ADC_DATA/GPIO1_A0_u) ; off-sheet CAN1_RX_M0
CAN1_TX_M0: J2.156(I2C3_SCL_M0/UART3_TX_M0/CAN1_TX_M0/AUDIOPWM_LOUT_N/ACODEC_ADC_CLK/GPIO1_A1_u) ; off-sheet CAN1_TX_M0
CAN2_RX_M0: J2.44(I2C2_SDA_M1/EBC_GDSP/CAN2_RX_M0/ISP_FLASH_TRIGIN/VOP_BT656_CLK_M1/GPIO4_B4_d) ; off-sheet CAN2_RX_M0
CAN2_TX_M0: J2.46(I2C2_SCL_M1/EBC_SDSHR/CAN2_TX_M0/I2S1_SDO3_M1/GPIO4_B5_d) ; off-sheet CAN2_TX_M0
CIF_CLKOUT_SOC: J2.52(CIF_CLKOUT/EBC_GDCLK/PWM11_IR_M1/GPIO4_C0_d) ; off-sheet CIF_CLKOUT_SOC
CLK_32K_OUT_GPIO0_B0: J2.112(CLK32K_IN/CLK32K_OUT0/PCIE30X2_BUTTONRSTn/GPIO0_B0_u) ; off-sheet CLK_32K_OUT_GPIO0_B0
EDP_EN_H_GPIO0_C5: J2.130(PWM6/SPI0_MISO_M0/PCIE30X2_WAKEn_M0/GPIO0_C5_d) ; off-sheet EDP_EN_H_GPIO0_C5  [project net EDP_EN]
EDP_ON_GPIO0_C3: J2.126(PWM4/VOP_PWM_M0/PCIE30X1_PERSTn_M0/MCU_JTAG_TRSTn/GPIO0_C3_d) ; off-sheet EDP_ON_GPIO0_C3  [project net EDP_ON]
EDP_PWM7: J2.132(PWM7_IR/SPI0_CS0_M0/PCIE30X2_PERSTn_M0/GPIO0_C6_d) ; off-sheet EDP_PWM7
EDP_TX_AUXN: J2.197(EDP_TX_AUXN) ; off-sheet EDP_TX_AUXN
EDP_TX_AUXP: J2.199(EDP_TX_AUXP) ; off-sheet EDP_TX_AUXP
EDP_TX_D0N: J2.213(EDP_TX_D0N) ; off-sheet EDP_TX_D0N
EDP_TX_D0P: J2.215(EDP_TX_D0P) ; off-sheet EDP_TX_D0P
EDP_TX_D1N: J2.209(EDP_TX_D1N) ; off-sheet EDP_TX_D1N
EDP_TX_D1P: J2.211(EDP_TX_D1P) ; off-sheet EDP_TX_D1P
EDP_TX_D2N: J2.205(EDP_TX_D2N) ; off-sheet EDP_TX_D2N
EDP_TX_D2P: J2.207(EDP_TX_D2P) ; off-sheet EDP_TX_D2P
EDP_TX_D3N: J2.201(EDP_TX_D3N) ; off-sheet EDP_TX_D3N
EDP_TX_D3P: J2.203(EDP_TX_D3P) ; off-sheet EDP_TX_D3P
EXT_EN: J2.249(EXT_EN) ; off-sheet EXT_EN
GMAC0_MCLKINOUT: J2.230(I2S2_SCLK_TX_M0/GMAC0_MCLKINOUT/UART7_CTSn_M0/SPI2_MISO_M0/GPIO2_C2_d) ; off-sheet GMAC0_MCLKINOUT
GMAC0_MDC: J2.232(I2S2_LRCK_TX_M0/GMAC0_MDC/UART9_RTSn_M0/SPI2_MOSI_M0/GPIO2_C3_d) ; off-sheet GMAC0_MDC
GMAC0_MDIO: J2.234(I2S2_SDO_M0/GMAC0_MDIO/UART9_CTSn_M0/SPI2_CS0_M0/GPIO2_C4_d) ; off-sheet GMAC0_MDIO
GMAC0_RSTn_GPIO2_D5: J2.77(LCDC_D5/VOP_BT656_D5_M0/SPI2_CS0_M1/PCIE30X2_WAKEn_M1/I2S1_SDI2_M2/GPIO2_D5_d) ; off-sheet GMAC0_RSTn_GPIO2_D5
GMAC0_RXCLK: J2.223(SDMMC1_D2/GMAC0_RXCLK/UART7_RX_M0/GPIO2_A5_u) ; off-sheet GMAC0_RXCLK
GMAC0_RXD0: J2.222(GMAC0_RXD0/UART1_CTSn_M0/SPI1_MISO_M0/GPIO2_B6_u) ; off-sheet GMAC0_RXD0
GMAC0_RXD1: J2.224(I2S2_SCLK_RX_M0/GMAC0_RXD1/UART6_RTSn_M0/SPI1_MOSI_M0/GPIO2_B7_d) ; off-sheet GMAC0_RXD1
GMAC0_RXD2: J2.219(SDMMC1_D0/GMAC0_RXD2/UART6_RX_M0/GPIO2_A3_u) ; off-sheet GMAC0_RXD2
GMAC0_RXD3: J2.221(SDMMC1_D1/GMAC0_RXD3/UART6_TX_M0/GPIO2_A4_u) ; off-sheet GMAC0_RXD3
GMAC0_RXDV_CRS: J2.226(I2S2_LRCK_RX_M0/GMAC0_RXDV_CRS/UART6_CTSn_M0/SPI1_CS0_M0/GPIO2_C0_d) ; off-sheet GMAC0_RXDV_CRS
GMAC0_TXCLK: J2.229(SDMMC1_CLK/GMAC0_TXCLK/UART9_TX_M0/GPIO2_B0_d) ; off-sheet GMAC0_TXCLK
GMAC0_TXD0: J2.216(GMAC0_TXD0/UART1_RX_M0/GPIO2_B3_u) ; off-sheet GMAC0_TXD0
GMAC0_TXD1: J2.218(GMAC0_TXD1/UART1_TX_M0/GPIO2_B4_u) ; off-sheet GMAC0_TXD1
GMAC0_TXD2: J2.225(SDMMC1_D3/GMAC0_TXD2/UART7_TX_M0/GPIO2_A6_u) ; off-sheet GMAC0_TXD2
GMAC0_TXD3: J2.227(SDMMC1_CMD/GMAC0_TXD3/UART9_RX_M0/GPIO2_A7_u) ; off-sheet GMAC0_TXD3
GMAC0_TXEN: J2.220(GMAC0_TXEN/UART1_RTSn_M0/SPI1_CLK_M0/GPIO2_B5_u) ; off-sheet GMAC0_TXEN
GMAC1_MCLKINOUT_M1: J2.54(CIF_CLKIN/EBC_SDCLK/GMAC1_MCLKINOUT_M1/UART1_CTSn_M1/I2S2_SCLK_RX_M1/GPIO4_C1_d) ; off-sheet GMAC1_MCLKINOUT_M1
GMAC1_MDC_M1: J2.48(CIF_HREF/EBC_SDLE/GMAC1_MDC_M1/UART1_RTSn_M1/I2S2_MCLK_M1/GPIO4_B6_d) ; off-sheet GMAC1_MDC_M1
GMAC1_MDIO_M1: J2.50(CIF_VSYNC/EBC_SDOE/GMAC1_MDIO_M1/I2S2_SCLK_TX_M1/GPIO4_B7_d) ; off-sheet GMAC1_MDIO_M1
GMAC1_RSTn_GPIO2_D7: J2.73(LCDC_D7/VOP_BT656_D7_M0/SPI2_MISO_M1/UART8_TX_M1/I2S1_SDO0_M2/GPIO2_D7_d) ; off-sheet GMAC1_RSTn_GPIO2_D7
GMAC1_RXCLK_M1: J2.45(CIF_D13/EBC_SDDO13/GMAC1_RXCLK_M1/UART7_RX_M2/PDM_SDI3_M1/GPIO4_A3_d) ; off-sheet GMAC1_RXCLK_M1
GMAC1_RXD0_M1: J2.34(CAM_CLKOUT0/EBC_SDCE1/GMAC1_RXD0_M1/SPI3_CS1_M0/I2S1_LRCK_RX_M1/GPIO4_A7_d) ; off-sheet GMAC1_RXD0_M1
GMAC1_RXD1_M1: J2.36(CAM_CLKOUT1/EBC_SDCE2/GMAC1_RXD1_M1/SPI3_MISO_M0/I2S1_SDO1_M1/GPIO4_B0_d) ; off-sheet GMAC1_RXD1_M1
GMAC1_RXD2_M1: J2.41(CIF_D11/EBC_SDDO11/GMAC1_RXD2_M1/PDM_SDI1_M1/GPIO4_A1_d) ; off-sheet GMAC1_RXD2_M1
GMAC1_RXD3_M1: J2.43(CIF_D12/EBC_SDDO12/GMAC1_RXD3_M1/UART7_TX_M2/PDM_SDI2_M1/GPIO4_A2_d) ; off-sheet GMAC1_RXD3_M1
GMAC1_RXDV_CRS_M1: J2.38(ISP_PRELIGHT_TRIG/EBC_SDCE3/GMAC1_RXDV_CRS_M1/I2S1_SDO2_M1/GPIO4_B1_d) ; off-sheet GMAC1_RXDV_CRS_M1
GMAC1_TXCLK_M1: J2.39(CIF_D10/EBC_SDDO10/GMAC1_TXCLK_M1/PDM_CLK1_M1/GPIO4_A0_d) ; off-sheet GMAC1_TXCLK_M1
GMAC1_TXD0_M1: J2.47(CIF_D14/EBC_SDDO14/GMAC1_TXD0_M1/UART9_TX_M2/I2S2_LRCK_TX_M1/GPIO4_A4_d) ; off-sheet GMAC1_TXD0_M1
GMAC1_TXD1_M1: J2.49(CIF_D15/EBC_SDDO15/GMAC1_TXD1_M1/UART9_RX_M2/I2S2_LRCK_RX_M1/GPIO4_A5_d) ; off-sheet GMAC1_TXD1_M1
GMAC1_TXD2_M1: J2.35(CIF_D8/EBC_SDDO8/GMAC1_TXD2_M1/UART1_TX_M1/PDM_CLK0_M1/GPIO3_D6_d) ; off-sheet GMAC1_TXD2_M1
GMAC1_TXD3_M1: J2.37(CIF_D9/EBC_SDDO9/GMAC1_TXD3_M1/UART1_RX_M1/PDM_SDI0_M1/GPIO3_D7_d) ; off-sheet GMAC1_TXD3_M1
GMAC1_TXEN_M1: J2.32(ISP_FLASHTRIGOUT/EBC_SDCE0/GMAC1_TXEN_M1/SPI3_CS0_M0/I2S1_SCLK_RX_M1/GPIO4_A6_d) ; off-sheet GMAC1_TXEN_M1
HDMI_TX_CLKN: J2.147(HDMI_TX_CLKN) ; off-sheet HDMI_TX_CLKN
HDMI_TX_CLKP: J2.149(HDMI_TX_CLKP) ; off-sheet HDMI_TX_CLKP
HDMI_TX_D0N: J2.155(HDMI_TX_D0N) ; off-sheet HDMI_TX_D0N
HDMI_TX_D0P: J2.153(HDMI_TX_D0P) ; off-sheet HDMI_TX_D0P
HDMI_TX_D1N: J2.159(HDMI_TX_D1N) ; off-sheet HDMI_TX_D1N
HDMI_TX_D1P: J2.157(HDMI_TX_D1P) ; off-sheet HDMI_TX_D1P
HDMI_TX_D2N: J2.163(HDMI_TX_D2N) ; off-sheet HDMI_TX_D2N
HDMI_TX_D2P: J2.161(HDMI_TX_D2P) ; off-sheet HDMI_TX_D2P
HDMI_TX_HPDIN: J2.143(HDMI_TX_HPDIN) ; off-sheet HDMI_TX_HPDIN
HDMITX_CEC_M0: J2.89(HDMITX_CEC_M0/SPI3_CS1_M1/GPIO4_D1_u) ; off-sheet HDMITX_CEC_M0
HOST_WAKE_BT_H_GPIO1_D3: J2.20(FSPI_CS0n/FLASH_CS0n/GPIO1_D3_u) ; off-sheet HOST_WAKE_BT_H_GPIO1_D3
HP_SNS: J2.244(HP_SNS) ; off-sheet HP_SNS
HPL_OUT: J2.242(HPL_OUT) ; off-sheet HPL_OUT
HPR_OUT: J2.246(HPR_OUT) ; off-sheet HPR_OUT
HUB_RST_GPIO1_A4_d: J2.8(I2S1_SCLK_RX_M0/UART4_RX_M0/PDM_CLK1_M0/SPDIF_TX_M0/GPIO1_A4_d) ; off-sheet HUB_RST_GPIO1_A4_d  [project net HUB_RST_]
I2C1_SCL: J2.146(I2C1_SCL/CAN0_TX_M0/PCIE30X1_BUTTONRSTn/MCU_JTAG_TDO/GPIO0_B3_u) ; off-sheet I2C1_SCL
I2C1_SDA: J2.148(I2C1_SDA/CAN0_RX_M0/PCIE20_BUTTONRSTn/MCU_JTAG_TCK/GPIO0_B4_u) ; off-sheet I2C1_SDA
I2C2_SCL_M0: J2.150(I2C2_SCL_M0/SPI0_CLK_M0/PCIE20_WAKEn_M0/PWM1_M1/GPIO0_B5_u) ; off-sheet I2C2_SCL_M0
I2C2_SDA_M0: J2.152(I2C2_SDA_M0/SPI0_MOSI_M0/PCIE20_PERSTn_M0/PWM2_M1/GPIO0_B6_u) ; off-sheet I2C2_SDA_M0
I2C3_SCL_M1: J2.74(LCDC_D20/VOP_BT1120_D11/GMAC1_TXD0_M0/I2C3_SCL_M1/PWM10_M0/GPIO3_B5_d) ; off-sheet I2C3_SCL_M1
I2C3_SDA_M1: J2.72(LCDC_D21/VOP_BT1120_D12/GMAC1_TXD1_M0/I2C3_SDA_M1/PWM11_IR_M0/GPIO3_B6_d) ; off-sheet I2C3_SDA_M1
I2C4_SCL_M0: J2.42(I2C4_SCL_M0/EBC_GDOE/ETH1_REFCLKO_25M_M1/SPI3_CLK_M0/I2S2_SDO_M1/GPIO4_B3_d) ; off-sheet I2C4_SCL_M0
I2C4_SDA_M0: J2.40(I2C4_SDA_M0/EBC_VCOM/GMAC1_RXER_M1/SPI3_MOSI_M0/I2S2_SDI_M1/GPIO4_B2_d) ; off-sheet I2C4_SDA_M0
I2C5_SCL-HDMI: J2.93(HDMITX_SCL/I2C5_SCL_M1/GPIO4_C7_u) ; off-sheet I2C5_SCL-HDMI
I2C5_SCL_M0: J2.78(LCDC_D18/VOP_BT1120_D9/GMAC1_RXDV_CRS_M0/I2C5_SCL_M0/PDM_SDI0_M2/GPIO3_B3_d) ; off-sheet I2C5_SCL_M0
I2C5_SDA-HDMI: J2.91(HDMITX_SDA/I2C5_SDA_M1/GPIO4_D0_u) ; off-sheet I2C5_SDA-HDMI
I2C5_SDA_M0: J2.76(LCDC_D19/VOP_BT1120_D10/GMAC1_RXER_M0/I2C5_SDA_M0/PDM_SDI1_M2/GPIO3_B4_d) ; off-sheet I2C5_SDA_M0
LVDS_EN_GPIO3_A2: J2.65(LCDC_D9/VOP_BT1120_D1/GMAC1_TXD2_M0/I2S3_MCLK_M0/SDMMC2_D1_M1/GPIO3_A2_d) ; off-sheet LVDS_EN_GPIO3_A2  [project net LVDS_EN]
LVDS_ON_GPIO3_A1: J2.67(LCDC_D8/VOP_BT1120_D0/SPI1_CS0_M1/PCIE30X1_PERSTn_M1/SDMMC2_D0_M1/GPIO3_A1_d) ; off-sheet LVDS_ON_GPIO3_A1  [project net LVDS_ON]
MIC1_INN: J2.250(MIC1_INN) ; off-sheet MIC1_INN
MIC1_INP: J2.248(MIC1_INP) ; off-sheet MIC1_INP
MIPI_CSI_RX_CLK0N: J2.103(MIPI_CSI_RX_CLK0N) ; off-sheet MIPI_CSI_RX_CLK0N
MIPI_CSI_RX_CLK0P: J2.101(MIPI_CSI_RX_CLK0P) ; off-sheet MIPI_CSI_RX_CLK0P
MIPI_CSI_RX_CLK1N: J2.99(MIPI_CSI_RX_CLK1N) ; off-sheet MIPI_CSI_RX_CLK1N
MIPI_CSI_RX_CLK1P: J2.97(MIPI_CSI_RX_CLK1P) ; off-sheet MIPI_CSI_RX_CLK1P
MIPI_CSI_RX_D0N: J2.119(MIPI_CSI_RX_D0N) ; off-sheet MIPI_CSI_RX_D0N
MIPI_CSI_RX_D0P: J2.117(MIPI_CSI_RX_D0P) ; off-sheet MIPI_CSI_RX_D0P
MIPI_CSI_RX_D1N: J2.115(MIPI_CSI_RX_D1N) ; off-sheet MIPI_CSI_RX_D1N
MIPI_CSI_RX_D1P: J2.113(MIPI_CSI_RX_D1P) ; off-sheet MIPI_CSI_RX_D1P
MIPI_CSI_RX_D2N: J2.111(MIPI_CSI_RX_D2N) ; off-sheet MIPI_CSI_RX_D2N
MIPI_CSI_RX_D2P: J2.109(MIPI_CSI_RX_D2P) ; off-sheet MIPI_CSI_RX_D2P
MIPI_CSI_RX_D3N: J2.107(MIPI_CSI_RX_D3N) ; off-sheet MIPI_CSI_RX_D3N
MIPI_CSI_RX_D3P: J2.105(MIPI_CSI_RX_D3P) ; off-sheet MIPI_CSI_RX_D3P
MIPI_DSI_TX0_CLKN: J2.133(MIPI_DSI_TX0_CLKN/LVDS_TX0_CLKN) ; off-sheet MIPI_DSI_TX0_CLKN
MIPI_DSI_TX0_CLKP: J2.131(MIPI_DSI_TX0_CLKP/LVDS_TX0_CLKP) ; off-sheet MIPI_DSI_TX0_CLKP
MIPI_DSI_TX0_D0N: J2.141(MIPI_DSI_TX0_D0N/LVDS_TX0_D0N) ; off-sheet MIPI_DSI_TX0_D0N
MIPI_DSI_TX0_D0P: J2.139(MIPI_DSI_TX0_D0P/LVDS_TX0_D0P) ; off-sheet MIPI_DSI_TX0_D0P
MIPI_DSI_TX0_D1N: J2.137(MIPI_DSI_TX0_D1N/LVDS_TX0_D1N) ; off-sheet MIPI_DSI_TX0_D1N
MIPI_DSI_TX0_D1P: J2.135(MIPI_DSI_TX0_D1P/LVDS_TX0_D1P) ; off-sheet MIPI_DSI_TX0_D1P
MIPI_DSI_TX0_D2N: J2.129(MIPI_DSI_TX0_D2N/LVDS_TX0_D2N) ; off-sheet MIPI_DSI_TX0_D2N
MIPI_DSI_TX0_D2P: J2.127(MIPI_DSI_TX0_D2P/LVDS_TX0_D2P) ; off-sheet MIPI_DSI_TX0_D2P
MIPI_DSI_TX0_D3N: J2.125(MIPI_DSI_TX0_D3N/LVDS_TX0_D3N) ; off-sheet MIPI_DSI_TX0_D3N
MIPI_DSI_TX0_D3P: J2.123(MIPI_DSI_TX0_D3P/LVDS_TX0_D3P) ; off-sheet MIPI_DSI_TX0_D3P
MIPI_DSI_TX0_RST_GPIO4_C3: J2.136(PWM14_M1/SPI3_CLK_M1/CAN1_RX_M1/PCIE30X2_CLKREQn_M2/I2S3_MCLK_M1/GPIO4_C2_d) ; off-sheet MIPI_DSI_TX0_RST_GPIO4_C3
MIPI_DSI_TX1_CLKN: J2.96(MIPI_DSI_TX1_CLKN) ; off-sheet MIPI_DSI_TX1_CLKN
MIPI_DSI_TX1_CLKP: J2.94(MIPI_DSI_TX1_CLKP) ; off-sheet MIPI_DSI_TX1_CLKP
MIPI_DSI_TX1_D0N: J2.104(MIPI_DSI_TX1_D0N) ; off-sheet MIPI_DSI_TX1_D0N
MIPI_DSI_TX1_D0P: J2.102(MIPI_DSI_TX1_D0P) ; off-sheet MIPI_DSI_TX1_D0P
MIPI_DSI_TX1_D1N: J2.100(MIPI_DSI_TX1_D1N) ; off-sheet MIPI_DSI_TX1_D1N
MIPI_DSI_TX1_D1P: J2.98(MIPI_DSI_TX1_D1P) ; off-sheet MIPI_DSI_TX1_D1P
MIPI_DSI_TX1_D2N: J2.92(MIPI_DSI_TX1_D2N) ; off-sheet MIPI_DSI_TX1_D2N
MIPI_DSI_TX1_D2P: J2.90(MIPI_DSI_TX1_D2P) ; off-sheet MIPI_DSI_TX1_D2P
MIPI_DSI_TX1_D3N: J2.88(MIPI_DSI_TX1_D3N) ; off-sheet MIPI_DSI_TX1_D3N
MIPI_DSI_TX1_D3P: J2.86(MIPI_DSI_TX1_D3P) ; off-sheet MIPI_DSI_TX1_D3P
MIPI_TX1_BL_PWM12_M0: J2.70(LCDC_D22/PWM12_M0/GMAC1_TXEN_M0/UART3_TX_M1/PDM_SDI2_M2/GPIO3_B7_d) ; off-sheet MIPI_TX1_BL_PWM12_M0
MIPI_TX1_RST_GPIO2_D4: J2.79(LCDC_D4/VOP_BT656_D4_M0/SPI2_CS1_M1/PCIE30X2_CLKREQn_M1/I2S1_SDI1_M2/GPIO2_D4_d) ; off-sheet MIPI_TX1_RST_GPIO2_D4
MIPI_TX1_RST_GPIO2_D6: J2.75(LCDC_D6/VOP_BT656_D6_M0/SPI2_MOSI_M1/PCIE30X2_PERSTn_M1/I2S1_SDI3_M2/GPIO2_D6_d) ; off-sheet MIPI_TX1_RST_GPIO2_D6
NTC_SARADC_VIN3: J2.5(SARADC_VIN3) ; off-sheet NTC_SARADC_VIN3
PCIE20_CLKREQn_M2_3V3_L: J2.2(I2S1_SDO1_M0/I2S1_SDI3_M0/PDM_SDI3_M0/PCIE20_CLKREQn_M2/ACODEC_ADC_DATAR/GPIO1_B0_d) ; off-sheet PCIE20_CLKREQn_M2_3V3_L
PCIE20_PERSTn_M2_3V3_L: J2.6(I2S1_SDO3_M0/I2S1_SDI1_M0/PDM_SDI1_M0/PCIE20_PERSTn_M2/GPIO1_B2_d) ; off-sheet PCIE20_PERSTn_M2_3V3_L
PCIE20_PRSNT_3V3_L_GPIO3_A6: J2.57(LCDC_D13/VOP_BT1120_CLK/GMAC1_TXCLK_M0/I2S3_SDI_M0/SDMMC2_CLK_M1/GPIO3_A6_d) ; off-sheet PCIE20_PRSNT_3V3_L_GPIO3_A6
PCIE20_REFCLKN: J2.184(PCIE20_REFCLKN) ; off-sheet PCIE20_REFCLKN
PCIE20_REFCLKP: J2.182(PCIE20_REFCLKP) ; off-sheet PCIE20_REFCLKP
PCIE20_RXN: J2.188(PCIE20_RXN/SATA2_RXN/QSGMII_RXN_M1) ; off-sheet PCIE20_RXN
PCIE20_RXP: J2.186(PCIE20_RXP/SATA2_RXP/QSGMII_RXP_M1) ; off-sheet PCIE20_RXP
PCIE20_TXN: J2.192(PCIE20_TXN/SATA2_TXN/QSGMII_TXN_M1) ; off-sheet PCIE20_TXN
PCIE20_TXP: J2.190(PCIE20_TXP/SATA2_TXP/QSGMII_TXP_M1) ; off-sheet PCIE20_TXP
PCIE20_WAKEn_M2_3V3_L: J2.4(I2S1_SDO2_M0/I2S1_SDI2_M0/PDM_SDI2_M0/PCIE20_WAKEn_M2/ACODEC_ADC_SYNC/GPIO1_B1_d) ; off-sheet PCIE20_WAKEn_M2_3V3_L
PWM3_IR: J2.124(PWM3_IR/EDP_HPDIN_M1/PCIE30X1_WAKEn_M0/MCU_JTAG_TMS/GPIO0_C2_d) ; off-sheet PWM3_IR
PWM13_M1: J2.144(PWM13_M1/SPI3_CS0_M1/SATA0_ACT_LED/UART9_RX_M1/I2S3_SDI_M1/GPIO4_C6_d) ; off-sheet PWM13_M1
RK809-CLK32K: J2.247(RK809-CLK32K) ; off-sheet RK809-CLK32K
RK809_PWRON: J2.251(RK809_PWRON) ; off-sheet RK809_PWRON
RK809_VDC: J2.252(RK809_VDC) ; off-sheet RK809_VDC
SARADC_VIN0_KEY/RECOVERY: J2.1(SARADC_VIN0_KEY/RECOVERY) ; off-sheet SARADC_VIN0_KEY/RECOVERY
SARADC_VIN2_HP_HOOK: J2.3(SARADC_VIN2_HP_HOOK) ; off-sheet SARADC_VIN2_HP_HOOK
SARADC_VIN4: J2.7(SARADC_VIN4) ; off-sheet SARADC_VIN4
SDMMC0_CLK: J2.206(SDMMC0_CLK/TEST_CLKOUT/UART5_TX_M0/CAN0_RX_M1/GPIO2_A2_d) ; off-sheet SDMMC0_CLK
SDMMC0_CMD: J2.204(SDMMC0_CMD/PWM10_M1/UART5_RX_M0/CAN0_TX_M1/GPIO2_A1_u) ; off-sheet SDMMC0_CMD
SDMMC0_D0: J2.196(SDMMC0_D0/UART2_TX_M1/UART6_TX_M1/PWM8_M1/GPIO1_D5_u) ; off-sheet SDMMC0_D0
SDMMC0_D1: J2.198(SDMMC0_D1/UART2_RX_M1/UART6_RX_M1/PWM9_M1/GPIO1_D6_u) ; off-sheet SDMMC0_D1
SDMMC0_D2: J2.200(SDMMC0_D2/ARMJTAG_TCK/UART5_CTSn_M0/GPIO1_D7_u) ; off-sheet SDMMC0_D2
SDMMC0_D3: J2.202(SDMMC0_D3/ARMJTAG_TMS/UART5_RTSn_M0/GPIO2_A0_u) ; off-sheet SDMMC0_D3
SDMMC0_DET_L: J2.208(SDMMC0_DET/SATA_CP_DET/PCIE30X1_CLKREQn_M0/GPIO0_A4_u) ; off-sheet SDMMC0_DET_L
SDMMC2_CLK_M0: J2.27(CIF_D5/EBC_SDDO5/SDMMC2_CLK_M0/I2S1_SDI1_M1/VOP_BT656_D5_M1/GPIO3_D3_d) ; off-sheet SDMMC2_CLK_M0
SDMMC2_CMD_M0: J2.25(CIF_D4/EBC_SDDO4/SDMMC2_CMD_M0/I2S1_SDI0_M1/VOP_BT656_D4_M1/GPIO3_D2_d) ; off-sheet SDMMC2_CMD_M0
SDMMC2_D0_M0: J2.17(CIF_D0/EBC_SDDO0/SDMMC2_D0_M0/I2S1_MCLK_M1/VOP_BT656_D0_M1/GPIO3_C6_d) ; off-sheet SDMMC2_D0_M0
SDMMC2_D1_M0: J2.19(CIF_D1/EBC_SDDO1/SDMMC2_D1_M0/I2S1_SCLK_TX_M1/VOP_BT656_D1_M1/GPIO3_C7_d) ; off-sheet SDMMC2_D1_M0
SDMMC2_D2_M0: J2.21(CIF_D2/EBC_SDDO2/SDMMC2_D2_M0/I2S1_LRCK_TX_M1/VOP_BT656_D2_M1/GPIO3_D0_d) ; off-sheet SDMMC2_D2_M0
SDMMC2_D3_M0: J2.23(CIF_D3/EBC_SDDO3/SDMMC2_D3_M0/I2S1_SDO0_M1/VOP_BT656_D3_M1/GPIO3_D1_d) ; off-sheet SDMMC2_D3_M0
SPI0_CLK_M1: J2.81(LCDC_D3/VOP_BT656_D3_M0/SPI0_CLK_M1/PCIE30X1_WAKEn_M1/I2S1_SDI0_M2/GPIO2_D3_d) ; off-sheet SPI0_CLK_M1
SPI0_CS0_M1: J2.83(LCDC_D2/VOP_BT656_D2_M0/SPI0_CS0_M1/PCIE30X1_CLKREQn_M1/I2S1_LRCK_TX_M2/GPIO2_D2_d) ; off-sheet SPI0_CS0_M1
SPI0_MISO_M1: J2.87(LCDC_D0/VOP_BT656_D0_M0/SPI0_MISO_M1/PCIE20X1_CLKREQn_M1/I2S1_MCLK_M2/GPIO2_D0_d) ; off-sheet SPI0_MISO_M1
SPI0_MOSI_M1: J2.85(LCDC_D1/VOP_BT656_D1_M0/SPI0_MOSI_M1/PCIE20X1_WAKEn_M1/I2S1_SCLK_TX_M2/GPIO2_D1_d) ; off-sheet SPI0_MOSI_M1
SPK_CTL_H_GPIO3_B0: J2.53(LCDC_D15/VOP_BT1120_D6/ETH1_REFCLKO_25M_M0/SDMMC2_PWREN_M1/GPIO3_B0_d) ; off-sheet SPK_CTL_H_GPIO3_B0
SPK_MUTE_H_GPIO3_A7: J2.55(LCDC_D14/VOP_BT1120_D5/GMAC1_RXCLK_M0/SDMMC2_DET_M1/GPIO3_A7_d) ; off-sheet SPK_MUTE_H_GPIO3_A7
SYS_LED_GPIO4_C5: J2.142(PWM12_M1/SPI3_MISO_M1/SATA1_ACT_LED/UART9_TX_M1/I2S3_SDO_M1/GPIO4_C5_d) ; off-sheet SYS_LED_GPIO4_C5
SYS_RESETn: J2.235(SYS_RESETn) ; off-sheet SYS_RESETn
TP0_INT_L_GPIO3_A3: J2.63(LCDC_D10/VOP_BT1120_D2/GMAC1_TXD3_M0/I2S3_SCLK_M0/SDMMC2_D2_M1/GPIO3_A3_d) ; off-sheet TP0_INT_L_GPIO3_A3
TP0_RST_L_GPIO3_A4: J2.61(LCDC_D11/VOP_BT1120_D3/GMAC1_RXD2_M0/I2S3_LRCK_M0/SDMMC2_D3_M1/GPIO3_A4_d) ; off-sheet TP0_RST_L_GPIO3_A4
TP1_INT_L_GPIO3_C0: J2.68(LCDC_D23/PWM13_M0/GMAC1_MCLKINOUT_M0/UART3_RX_M1/PDM_SDI3_M2/GPIO3_C0_d) ; off-sheet TP1_INT_L_GPIO3_C0
TP1_RST_L_GPIO3_C1: J2.66(LCDC_HSYNC/VOP_BT1120_D13/SPI1_MOSI_M1/PCIE20_PERSTn_M1/I2S1_SDO2_M2/GPIO3_C1_d) ; off-sheet TP1_RST_L_GPIO3_C1
UART0_CTSn: J2.134(HDMITX_CEC_M1/PWM0_M1/UART0_CTSn/GPIO0_C7_d) ; off-sheet UART0_CTSn
UART0_RTSn: J2.128(PWM5/SPI0_CS1_M0/UART0_RTSn/GPIO0_C4_d) ; off-sheet UART0_RTSn
UART0_RX: J2.120(PWM1_M0/GPUAVS/UART0_RX/GPIO0_C0_d) ; off-sheet UART0_RX
UART0_TX: J2.122(PWM2_M0/NPUAVS/UART0_TX/MCU_JTAG_TDI/GPIO0_C1_d) ; off-sheet UART0_TX
UART2_RX_M0: J2.116(UART2_RX_M0/GPIO_D0_u) ; off-sheet UART2_RX_M0
UART2_TX_M0: J2.118(UART2_TX_M0/GPIO_D1_u) ; off-sheet UART2_TX_M0
UART4_RX_M1: J2.82(LCDC_D16/VOP_BT1120_D7/GMAC1_RXD0_M0/UART4_RX_M1/PWM8_M0/GPIO3_B1_d) ; off-sheet UART4_RX_M1
UART4_TX_M1: J2.80(LCDC_D17/VOP_BT1120_D8/GMAC1_RXD1_M0/UART4_TX_M1/PWM9_M0/GPIO3_B2_d) ; off-sheet UART4_TX_M1
UART5_RX_M1: J2.62(LCDC_DEN/VOP_BT1120_D15/SPI1_CLK_M1/UART5_RX_M1/I2S1_SCLK_RX_M2/GPIO3_C3_d) ; off-sheet UART5_RX_M1
UART5_TX_M1: J2.64(LCDC_VSYNC/VOP_BT1120_D14/SPI1_MISO_M1/UART5_TX_M1/I2S1_SDO3_M2/GPIO3_C2_d) ; off-sheet UART5_TX_M1
UART7_RX_M1: J2.58(PWM15_IR_M0/SPDIF_TX_M1/GMAC1_MDIO_M0/UART7_RX_M1/I2S1_LRCK_RX_M2/GPIO3_C5_d) ; off-sheet UART7_RX_M1
UART7_TX_M1: J2.60(PWM14_M0/VOP_PWM_M1/GMAC1_MDC_M0/UART7_TX_M1/PDM_CLK1_M2/GPIO3_C4_d) ; off-sheet UART7_TX_M1
UART8_CTSn_M0: J2.233(SDMMC1_DET/I2C4_SCL_M1/UART8_CTSn_M0/CAN2_TX_M1/GPIO2_B2_u) ; off-sheet UART8_CTSn_M0
UART8_RTSn_M0: J2.231(SDMMC1_PWREN/I2C4_SDA_M1/UART8_RTSn_M0/CAN2_RX_M1/GPIO2_B1_d) ; off-sheet UART8_RTSn_M0
UART8_RX_M0: J2.238(CLK32K_OUT1/UART8_RX_M0/SPI1_CS1_M0/GPIO2_C6_d) ; off-sheet UART8_RX_M0
UART8_TX_M0: J2.236(I2S2_SDI_M0/GMAC0_RXER/UART8_TX_M0/SPI2_CS1_M0/GPIO2_C5_d) ; off-sheet UART8_TX_M0
USB1_PWREN_H_GPIO3_A5: J2.59(LCDC_D12/VOP_BT1120_D4/GMAC1_RXD3_M0/I2S3_SDO_M0/SDMMC2_CMD_M1/GPIO3_A5_d) ; off-sheet USB1_PWREN_H_GPIO3_A5
USB2_HOST2_DM: J2.28(USB2_HOST2_DM) ; off-sheet USB2_HOST2_DM
USB2_HOST2_DP: J2.26(USB2_HOST2_DP) ; off-sheet USB2_HOST2_DP
USB2_HOST2_PWREN_H_GPIO0_A6: J2.110(GPU_PWREN/SATA_CP_POD/PCIE30X2_CLKREQn_M0/GPIO0_A6_d) ; off-sheet USB2_HOST2_PWREN_H_GPIO0_A6
USB2_HOST3_DM: J2.24(USB2_HOST3_DM) ; off-sheet USB2_HOST3_DM
USB2_HOST3_DP: J2.22(USB2_HOST3_DP) ; off-sheet USB2_HOST3_DP
USB2_PWREN_H_GPIO4_C3: J2.138(PWM15_IR_M1/SPI3_MOSI_M1/CAN1_TX_M1/PCIE30X2_WAKEn_M2/I2S3_SCLK_M1/GPIO4_C3_d) ; off-sheet USB2_PWREN_H_GPIO4_C3
USB3_HOST1_DM: J2.169(USB3_HOST1_DM) ; off-sheet USB3_HOST1_DM
USB3_HOST1_DP: J2.167(USB3_HOST1_DP) ; off-sheet USB3_HOST1_DP
USB3_HOST1_PWREN_H_GPIO3_A0: J2.71(LCDC_CLK/VOP_BT656_CLK_M0/SPI2_CLK_M1/UART8_RX_M1/I2S1_SDO1_M2/GPIO3_A0_d) ; off-sheet USB3_HOST1_PWREN_H_GPIO3_A0
USB3_HOST1_SSRXN: J2.175(USB3_HOST1_SSRXN/SATA1_RXN/QSGMII_RXN_M0) ; off-sheet USB3_HOST1_SSRXN
USB3_HOST1_SSRXP: J2.177(USB3_HOST1_SSRXP/SATA1_RXP/QSGMII_RXP_M0) ; off-sheet USB3_HOST1_SSRXP
USB3_HOST1_SSTXN: J2.171(USB3_HOST1_SSTXN/SATA1_TXN/QSGMII_TXN_M0) ; off-sheet USB3_HOST1_SSTXN
USB3_HOST1_SSTXP: J2.173(USB3_HOST1_SSTXP/SATA1_TXP/QSGMII_TXP_M0) ; off-sheet USB3_HOST1_SSTXP
USB3_OTG0_DM: J2.189(USB3_OTG0_DM) ; off-sheet USB3_OTG0_DM
USB3_OTG0_DP: J2.187(USB3_OTG0_DP) ; off-sheet USB3_OTG0_DP
USB3_OTG0_ID: J2.193(USB3_OTG0_ID) ; off-sheet USB3_OTG0_ID
USB3_OTG0_SSRXN: J2.183(USB3_OTG0_SSRXN/SATA0_RXN) ; off-sheet USB3_OTG0_SSRXN
USB3_OTG0_SSRXP: J2.185(USB3_OTG0_SSRXP/SATA0_RXP) ; off-sheet USB3_OTG0_SSRXP
USB3_OTG0_SSTXN: J2.179(USB3_OTG0_SSTXN/SATA0_TXN) ; off-sheet USB3_OTG0_SSTXN
USB3_OTG0_SSTXP: J2.181(USB3_OTG0_SSTXP/SATA0_TXP) ; off-sheet USB3_OTG0_SSTXP
USB3_OTG0_VBUSDET: J2.191(USB3_OTG0_VBUSDET) ; off-sheet USB3_OTG0_VBUSDET
USB3_PWREN_H_GPIO4_C4: J2.140(EDP_HPDIN_M0/SPDIF_TX_M2/SATA2_ACT_LED/PCIE30X2_PERSTn_M2/I2S3_LRCK_M1/GPIO4_C4_d) ; off-sheet USB3_PWREN_H_GPIO4_C4
USB_OTG_PWREN_H_GPIO0_A5: J2.212(SDMMC0_PWREN/SATA_MP_SWITCH/PCIE20_CLKREQn_M0/GPIO0_A5_d) ; off-sheet USB_OTG_PWREN_H_GPIO0_A5
WIFI_PWREN_L_GPIO0_B7: J2.114(PWM0-M0/CPUAVS/GPIO0_B7_d) ; off-sheet WIFI_PWREN_L_GPIO0_B7
WIFI_REG_ON_H_GPIO3_D5: J2.33(CIF_D7/EBC_SDDO7/SDMMC2_PWREN_M0/I2S1_SDI3_M1/VOP_BT656_D7_M1/GPIO3_D5_d) ; off-sheet WIFI_REG_ON_H_GPIO3_D5
WIFI_WAKE_HOST_H_GPIO3_D4: J2.29(CIF_D6/EBC_SDDO6/SDMMC2_DET_M0/I2S1_SDI2_M1/VOP_BT656_D6_M1/GPIO3_D4_d) ; off-sheet WIFI_WAKE_HOST_H_GPIO3_D4

Not connected (* = marked no-connect by the designer): J2 160(PCIE30_RX1N) 162(PCIE30_RX1P) 164(PCIE30_RX0N) 166(PCIE30_RX0P) 168(PCIE30_TX1N) 170(PCIE30_TX1P) 172(PCIE30_TX0N) 174(PCIE30_TX0P) 176(PCIE30_REFCLKN_IN) 178(PCIE30_REFCLKP_IN) 239(BATDIV) 241(SNSP) 243(SNSN)

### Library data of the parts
C26-C29 = C-0805_Dup1: Manufacture: 三星¦国巨¦村田; Part Name: 贴片电容; Part Number: C020102120075; ID: 75; DSC3: X5R; DSC1: ±20%; PCB Footprint: C0603
J2 = ATMD097-AED4S-5F_5
R17 = R-0805_Dup1: Part Number: C011002081448; Part Name: 贴片电阻; ID: 1,448; DSC2: 1/8W; DSC1: ±1%; ERP Number: 1010200199

## Sheet P06.SchDoc
size 297 x 209 mm
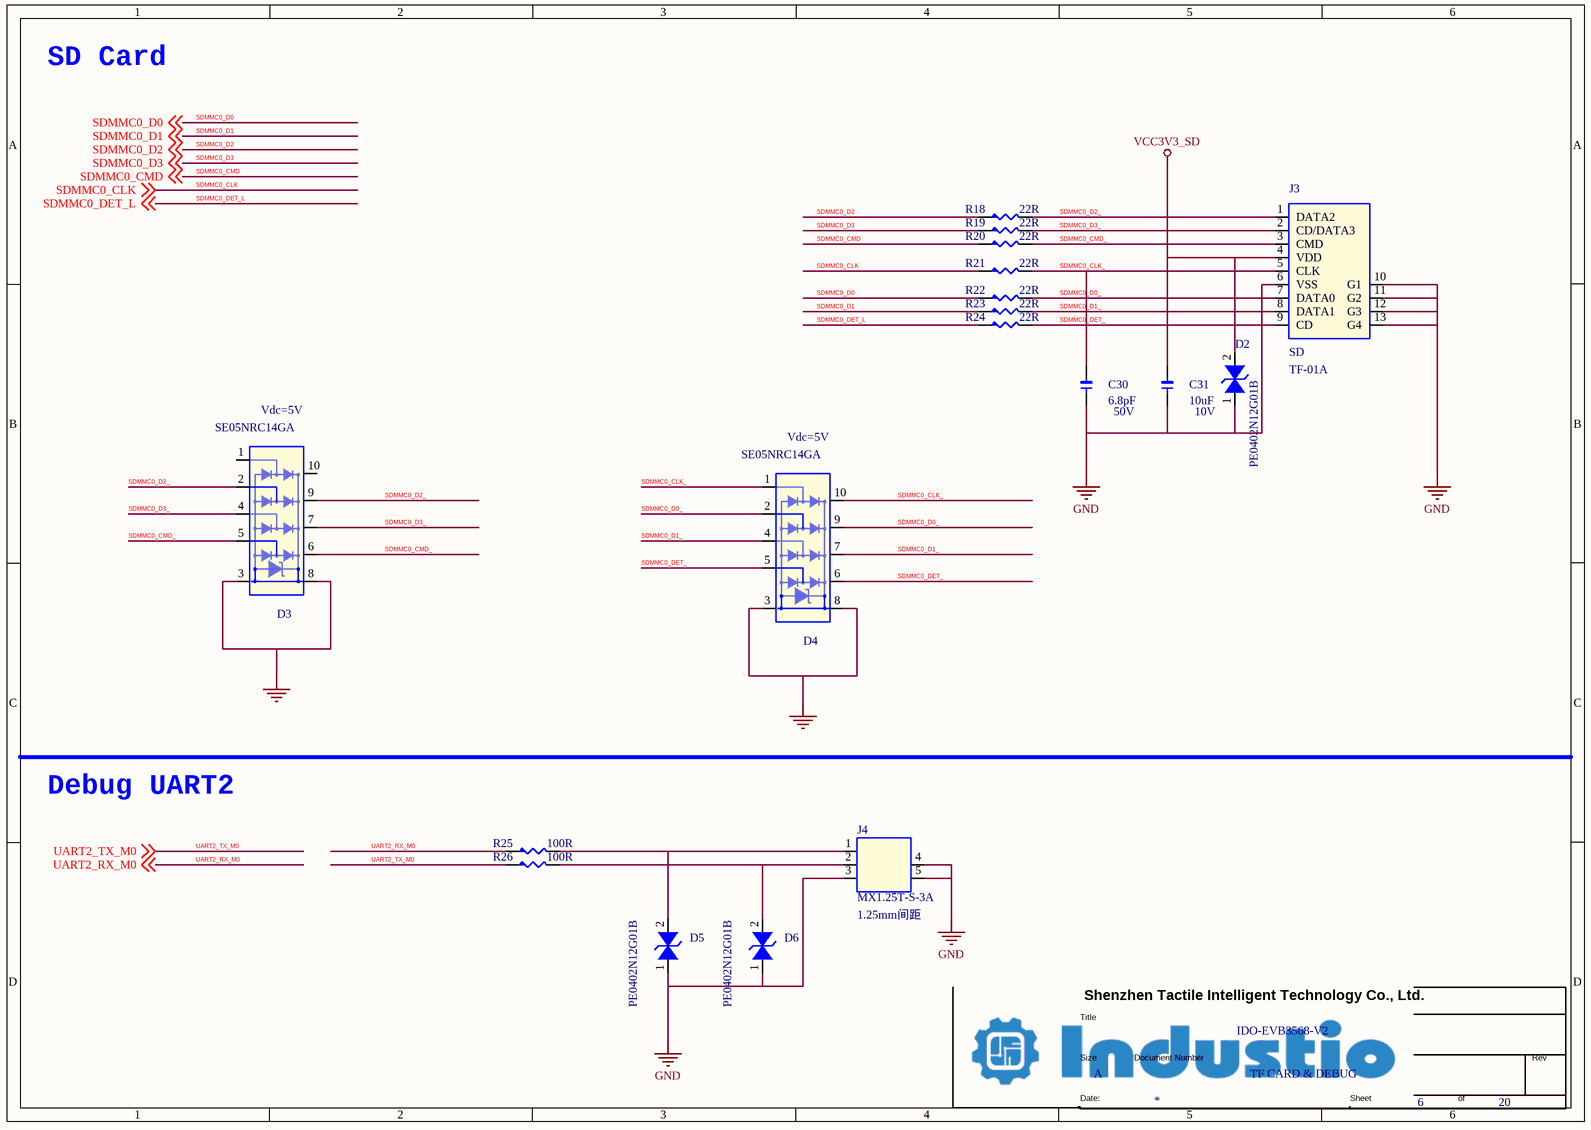
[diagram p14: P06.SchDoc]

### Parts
(Parts that share a designator on the sheet are numbered #1, #2 ... from top to bottom, then left to right.)
*#5  Doc: TF CARD & DEBUG  Title: IDO-EVB3568-V2  Page Size: A  Page Number: 6  Page Count: 20  (hidden comment: TitleBlock1)  (graphical)
C30  6.8pF  DSC2: 50V  [1206]
C31  10uF  DSC2: 10V  [1206]
D2  PE0402N12G01B  [V0402]
D3  SE05NRC14GA  DSC2: Vdc=5V  [DFN2510-10L]
D4  SE05NRC14GA  DSC2: Vdc=5V  [DFN2510-10L]
D5  PE0402N12G01B  [V0402]
D6  PE0402N12G01B  [V0402]
J3  SD  [TF-01A]
J4  MX1.25T-S-3A  DSC2: 1.25mm间距  [MX125T-S-3A]
R18  22R  [R0402]
R19  22R  [R0402]
R20  22R  [R0402]
R21  22R  [R0402]
R22  22R  [R0402]
R23  22R  [R0402]
R24  22R  [R0402]
R25  100R  [R0402]
R26  100R  [R0402]

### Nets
GND: C30.1 C31.1 D2.1(I/O2) D3.3 D3.8 D4.3 D4.8 D5.1(I/O2) D6.1(I/O2) J3.6(VSS) J3.10(G1) J3.11(G2) J3.12(G3) J3.13(G4) J4.3 J4.4 J4.5  [project net EDP_TX_AUXP_]
VCC3V3_SD: C31.2 D2.2(I/O1) J3.4(VDD)
SDMMC0_CLK: R21.1 ; off-sheet SDMMC0_CLK
SDMMC0_CLK_: C30.2 D4.1 D4.10 J3.5(CLK) R21.2
SDMMC0_CMD: R20.1 ; off-sheet SDMMC0_CMD
SDMMC0_CMD_: D3.5 D3.6 J3.3(CMD) R20.2
SDMMC0_D0: R22.1 ; off-sheet SDMMC0_D0
SDMMC0_D0_: D4.2 D4.9 J3.7(DATA0) R22.2
SDMMC0_D1: R23.1 ; off-sheet SDMMC0_D1
SDMMC0_D1_: D4.4 D4.7 J3.8(DATA1) R23.2
SDMMC0_D2: R18.1 ; off-sheet SDMMC0_D2
SDMMC0_D2_: D3.2 D3.9 J3.1(DATA2) R18.2
SDMMC0_D3: R19.1 ; off-sheet SDMMC0_D3
SDMMC0_D3_: D3.4 D3.7 J3.2(CD/DATA3) R19.2
SDMMC0_DET_: D4.5 D4.6 J3.9(CD) R24.2
SDMMC0_DET_L: R24.1 ; off-sheet SDMMC0_DET_L
UART2_RX_M0: R25.1 ; off-sheet UART2_RX_M0
UART2_TX_M0: R26.1 ; off-sheet UART2_TX_M0
NetD5_2: D5.2(I/O1) J4.1 R25.2
NetD6_2: D6.2(I/O1) J4.2 R26.2

Not connected (* = marked no-connect by the designer): D3 1 10

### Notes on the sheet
- SD Card
- Debug UART2

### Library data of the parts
C30 = C-0402_Dup1: Manufacture: 三星¦国巨¦村田; Part Name: 贴片电容; Part Number: C020102120018; PCB Footprint: C0402; ID: 18; DSC3: C0G; DSC1: ±0.25PF; ERP Number: 1010200056
C31 = C-0603_Dup1: Manufacture: 三星¦国巨¦村田; Part Name: 贴片电容; Part Number: C020102120071; ID: 71; DSC3: X5R; DSC1: ±20%; ERP Number: 1010200076; PCB Footprint: C0603
D2 D5 = DI-ESD: ESD 0402; Manufacturer: INPAQ; Manufacture P/N: MLVG04021R0UV18; Part Number: C040504013980; Manufacture: 硕凯; PN Type: Varistor; DSC1: 双向; DSC2: Vdc=12V; DSC4: Vc=40V; DSC5: Cj=0.05pF; ID: 1; Solder: 推荐
D3 D4 = DI-ESD-SE05NRC14GA: Part Name: ESD; Part Number: C040504013981; Manufacture: 硕凯; DSC1: 双向; DSC3: Vbr=8V; DSC4: Vc=20V; DSC5: Cj=0.4pF; ID: 8; Solder: 推荐
D6 = DI-ESD: ESD 0402; Manufacturer: INPAQ; Manufacture P/N: MLVG04021R0UV18; Part Number: C040504013980; Manufacture: 硕凯; PN Type: Varistor; Solder: 推荐; ID: 1; DSC5: Cj=0.05pF; DSC4: Vc=40V; DSC2: Vdc=12V; DSC1: 双向
J3 = J-TF-01A: Part Name: SD卡座; Part Number: J080102980002; ID: 2; DSC5: XKTF-N02-N(星坤); DSC4: KLM-1007（九龙熹）; DSC3: 贴片; DSC1: 自弹式 MicroSD卡(TF卡) 卡座 外焊 外扣,无弹片 本体最大高度：2mm
J4 = J-A-3P: Part Number: J020102800059; ID: 7; DSC6: X9821WVS-03-9TSN(星坤); DSC5: JLX-1.25T-3AB(九龙熹); DSC4: 米黄色胶壳 耐高温; DSC3: 立贴; DSC1: 3p
R18-R23 = R-0402_Dup3: Part Number: C011002080262; Part Name: 贴片电阻; DSC2: 1/16W; DSC1: ±5%; ERP Number: 1010200173
R24 = R-0402_Dup3: Part Name: 贴片电阻; Part Number: C011002080262; ERP Number: 1010200173; DSC1: ±5%; DSC2: 1/16W
R25 R26 = R-0402_Dup4: Part Name: 贴片电阻; Part Number: C011002080630; ERP Number: 1010200450; DSC1: ±1%; DSC2: 1/16W; ID: 630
